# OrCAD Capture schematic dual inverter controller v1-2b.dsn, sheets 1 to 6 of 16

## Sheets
1 Resolver B: size B; rev: V1.2B; company: Wolfspeed; note: 535 W Research Center Blvd.; note: Fayetteville, AR, 72701
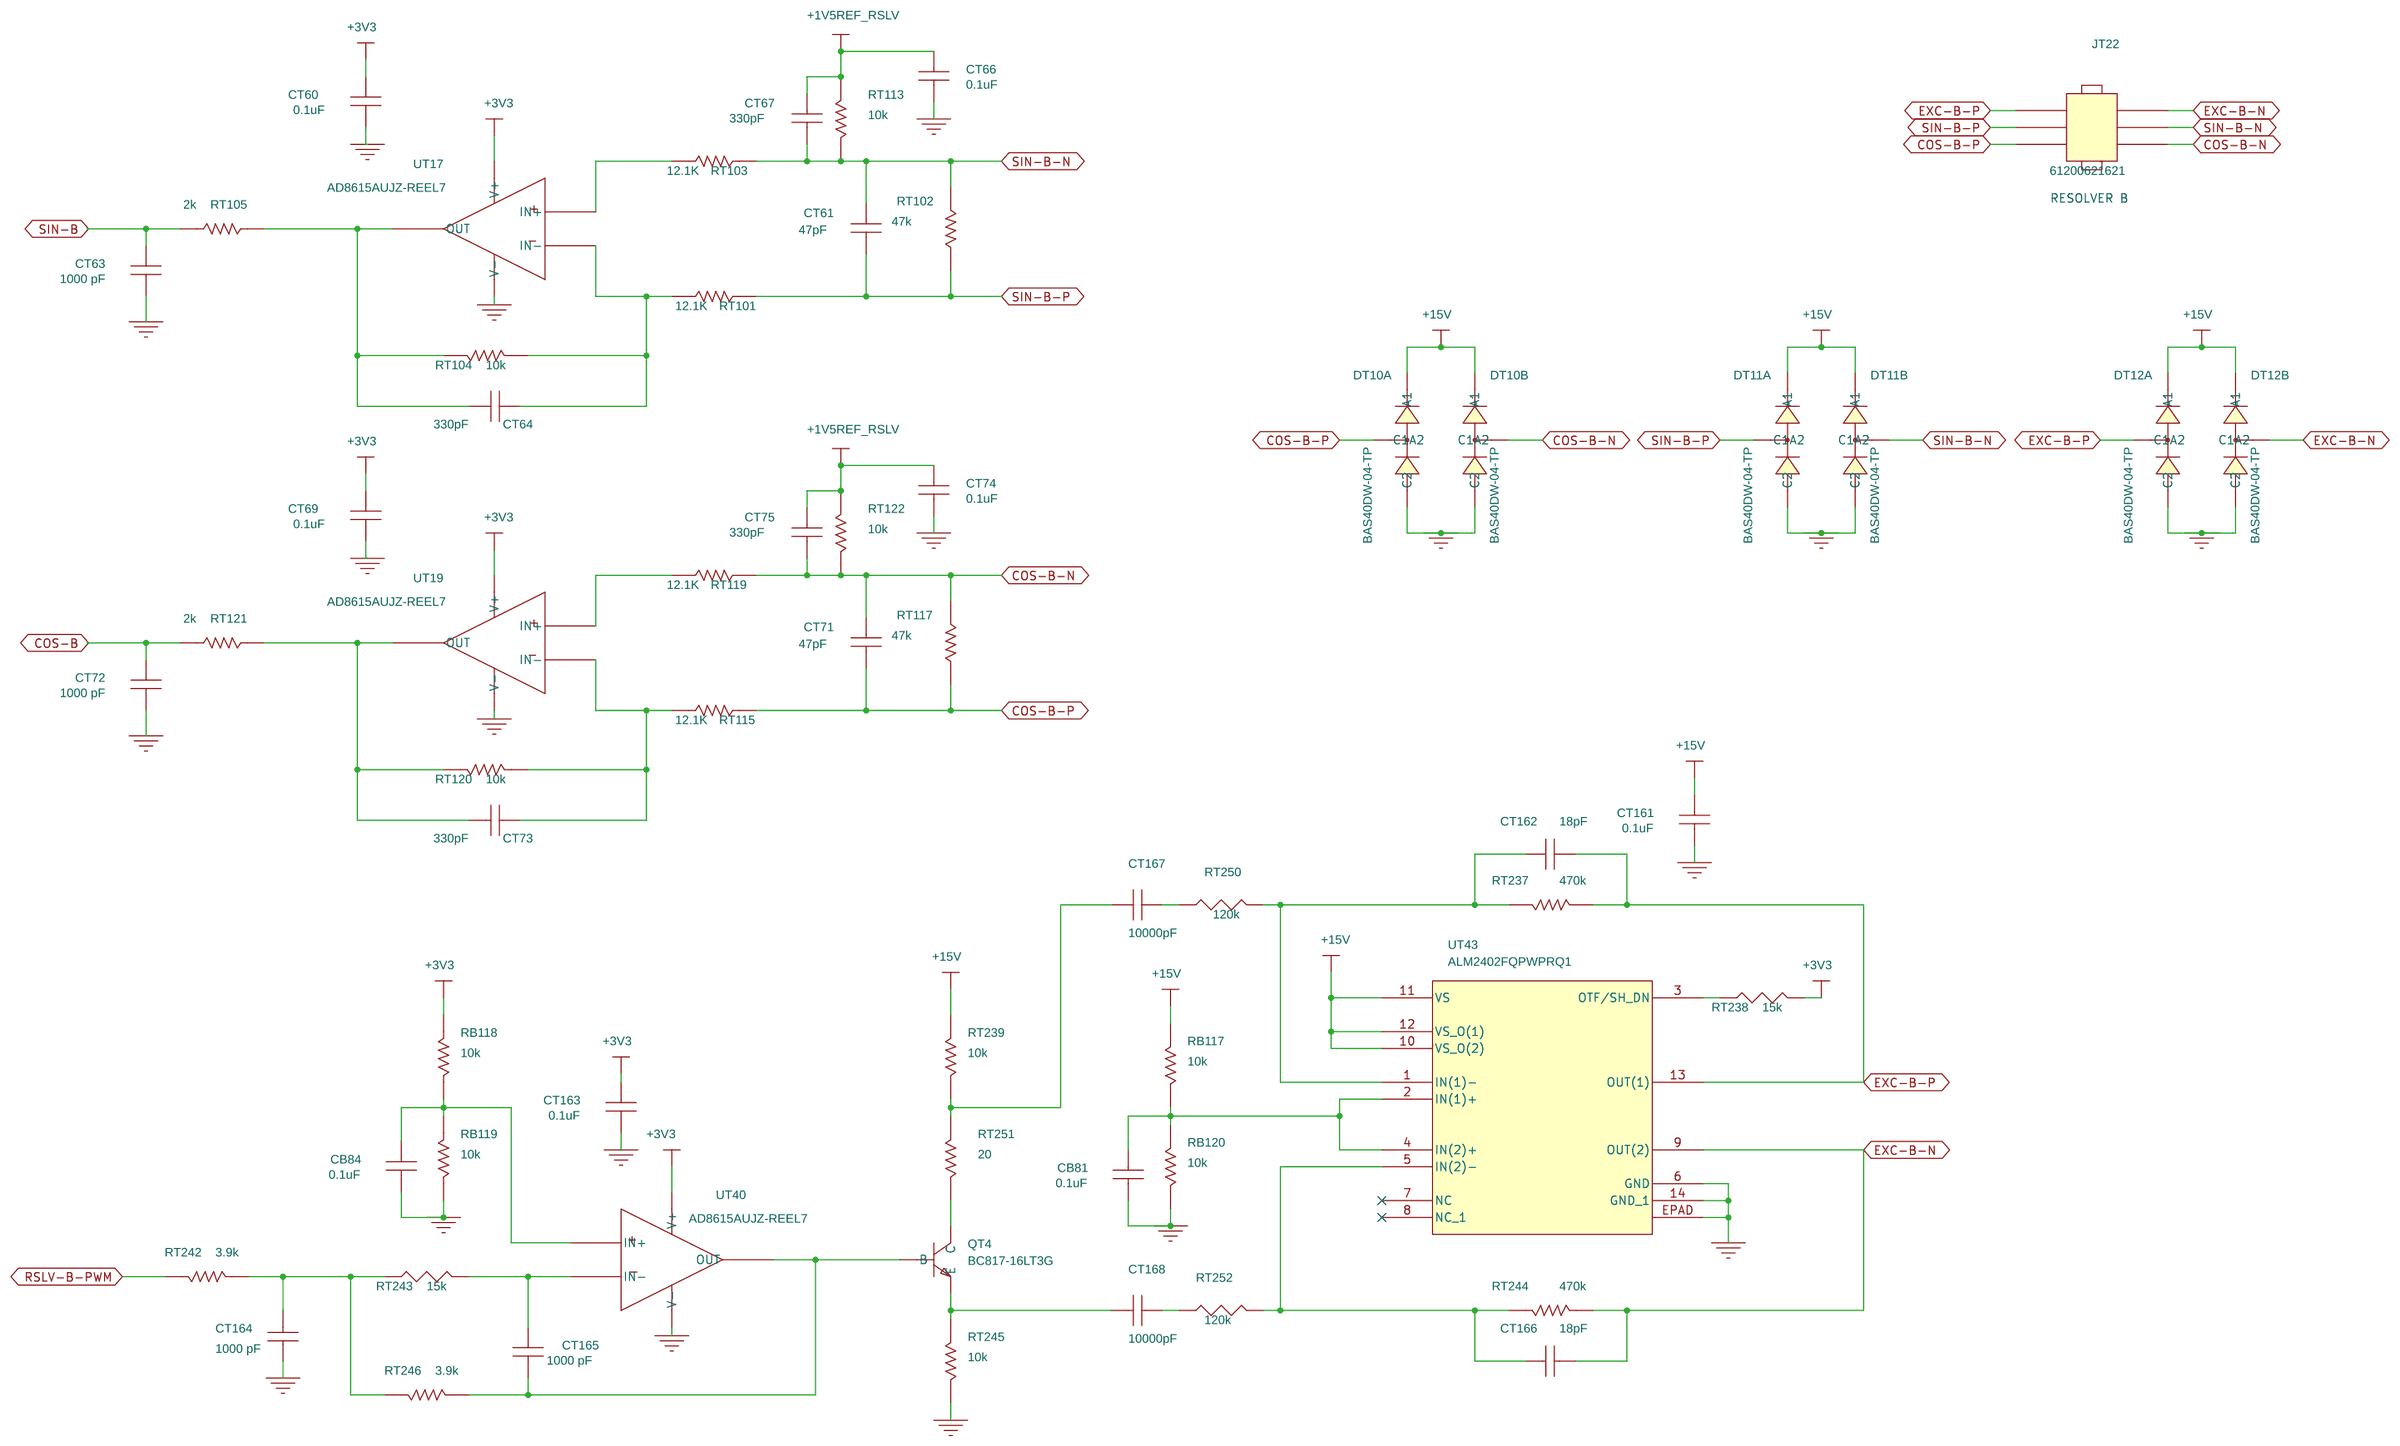
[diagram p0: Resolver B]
2 Resolver A: size B
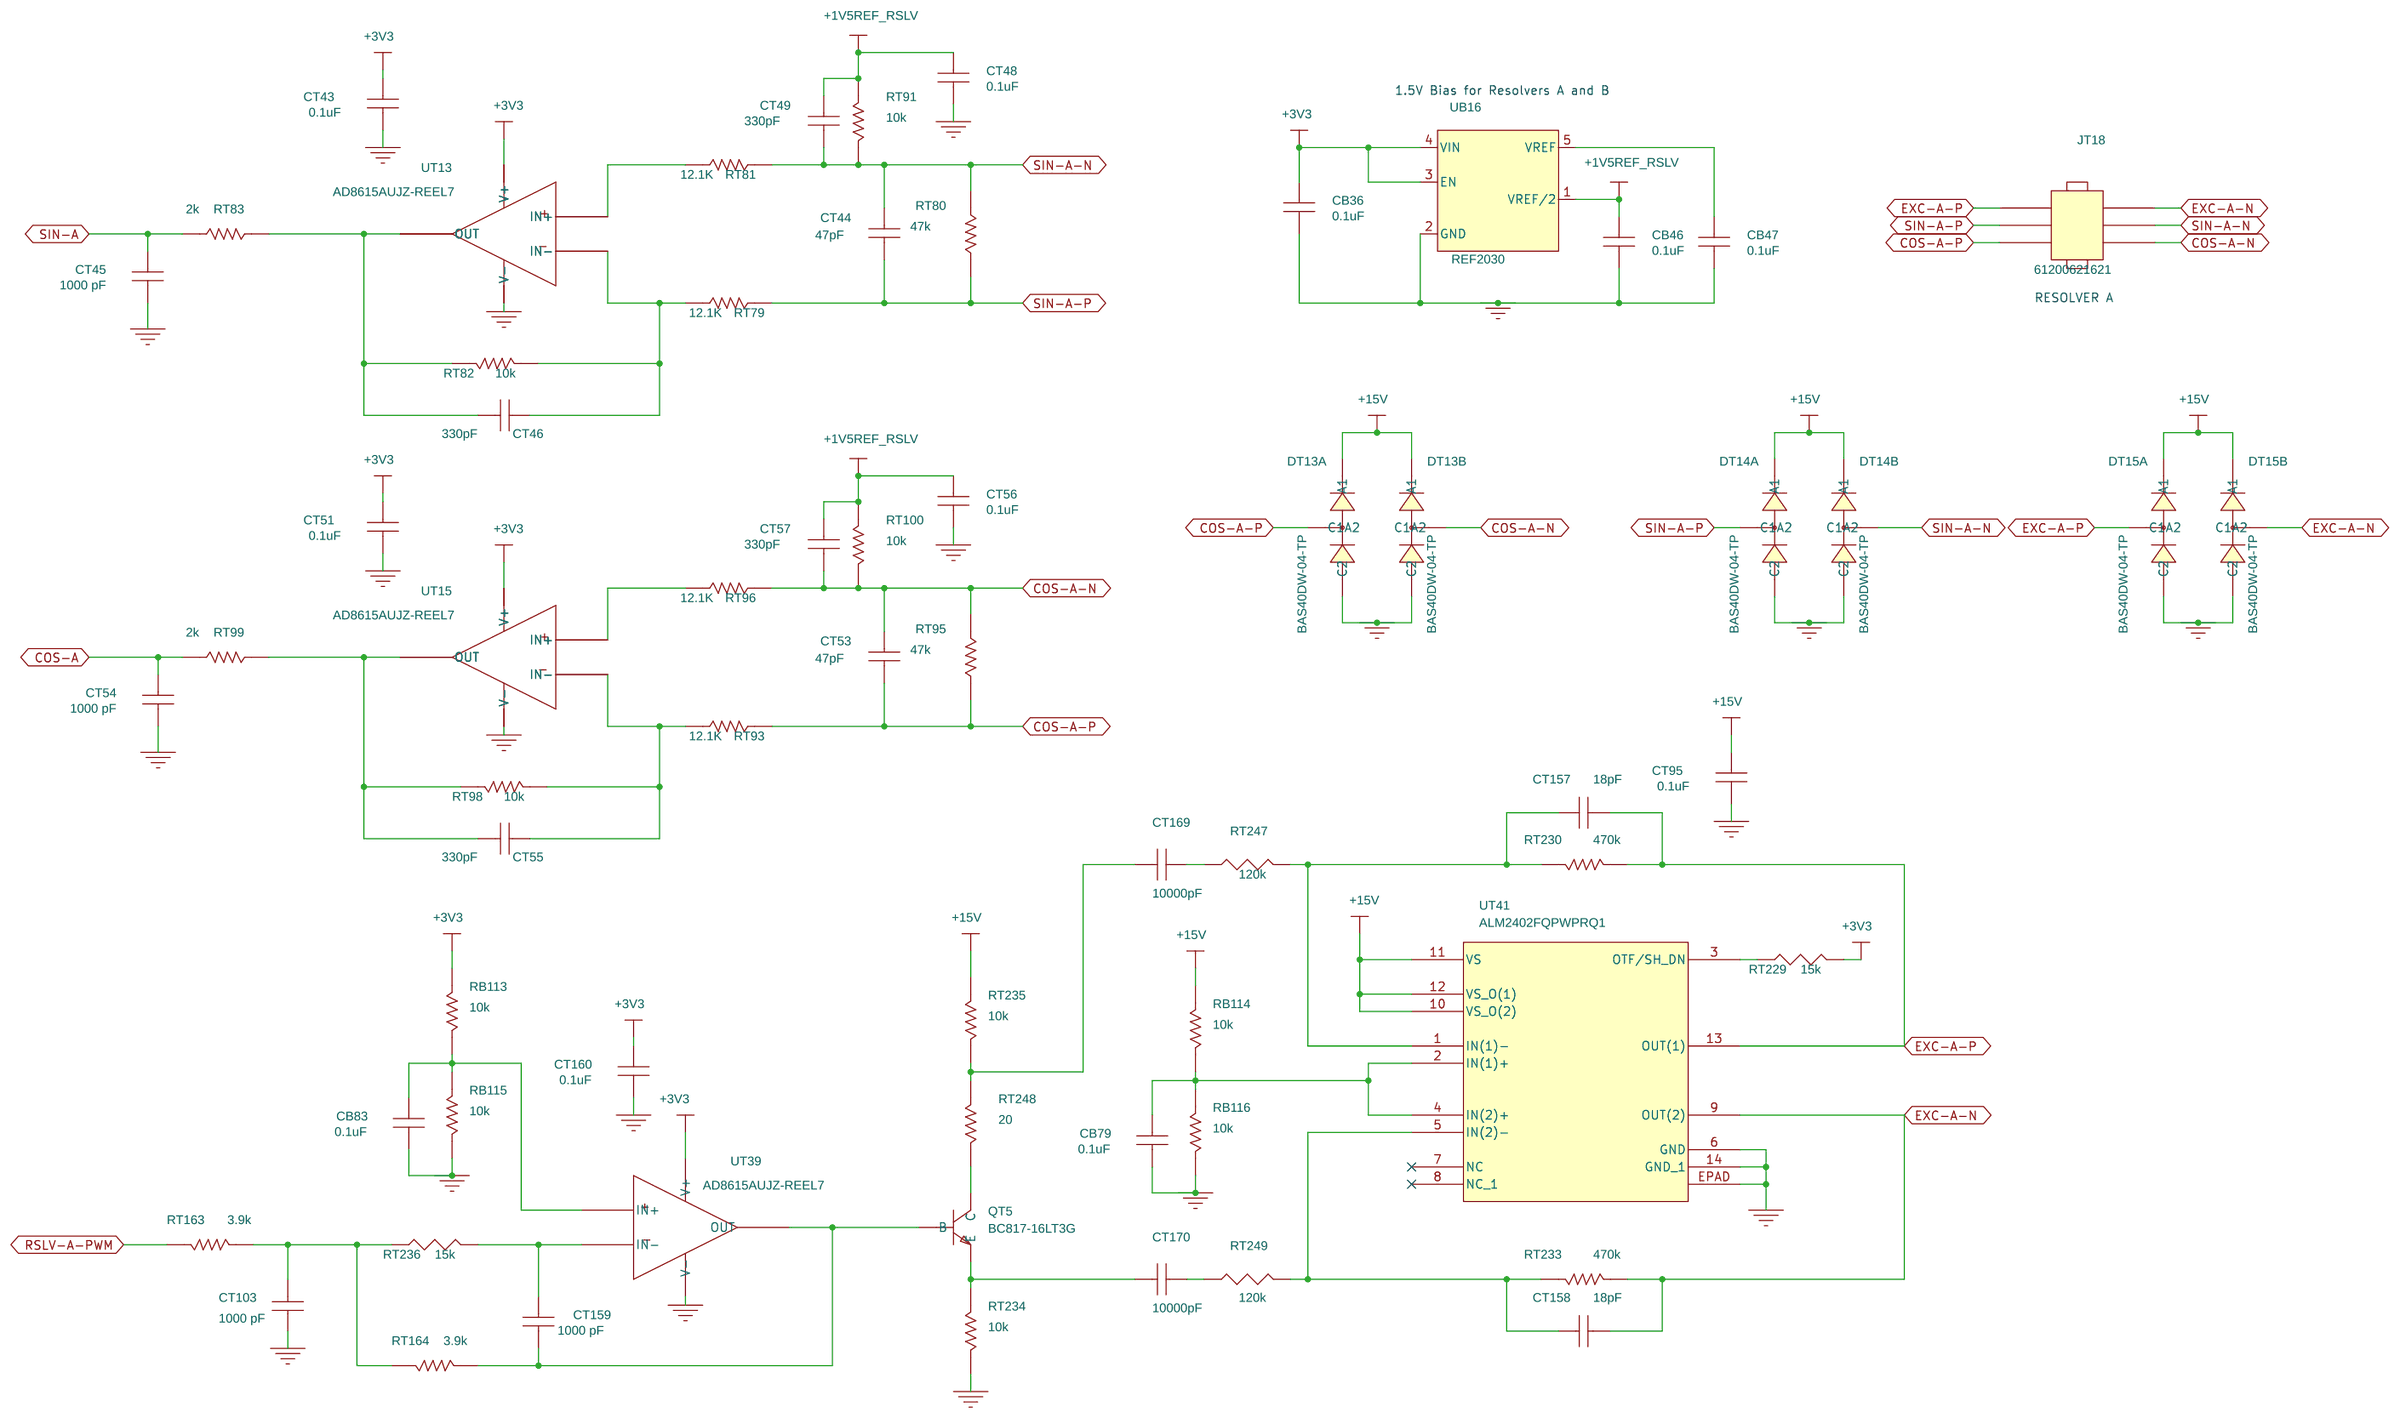
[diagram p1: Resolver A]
3 Test Points: size B; title: Controller
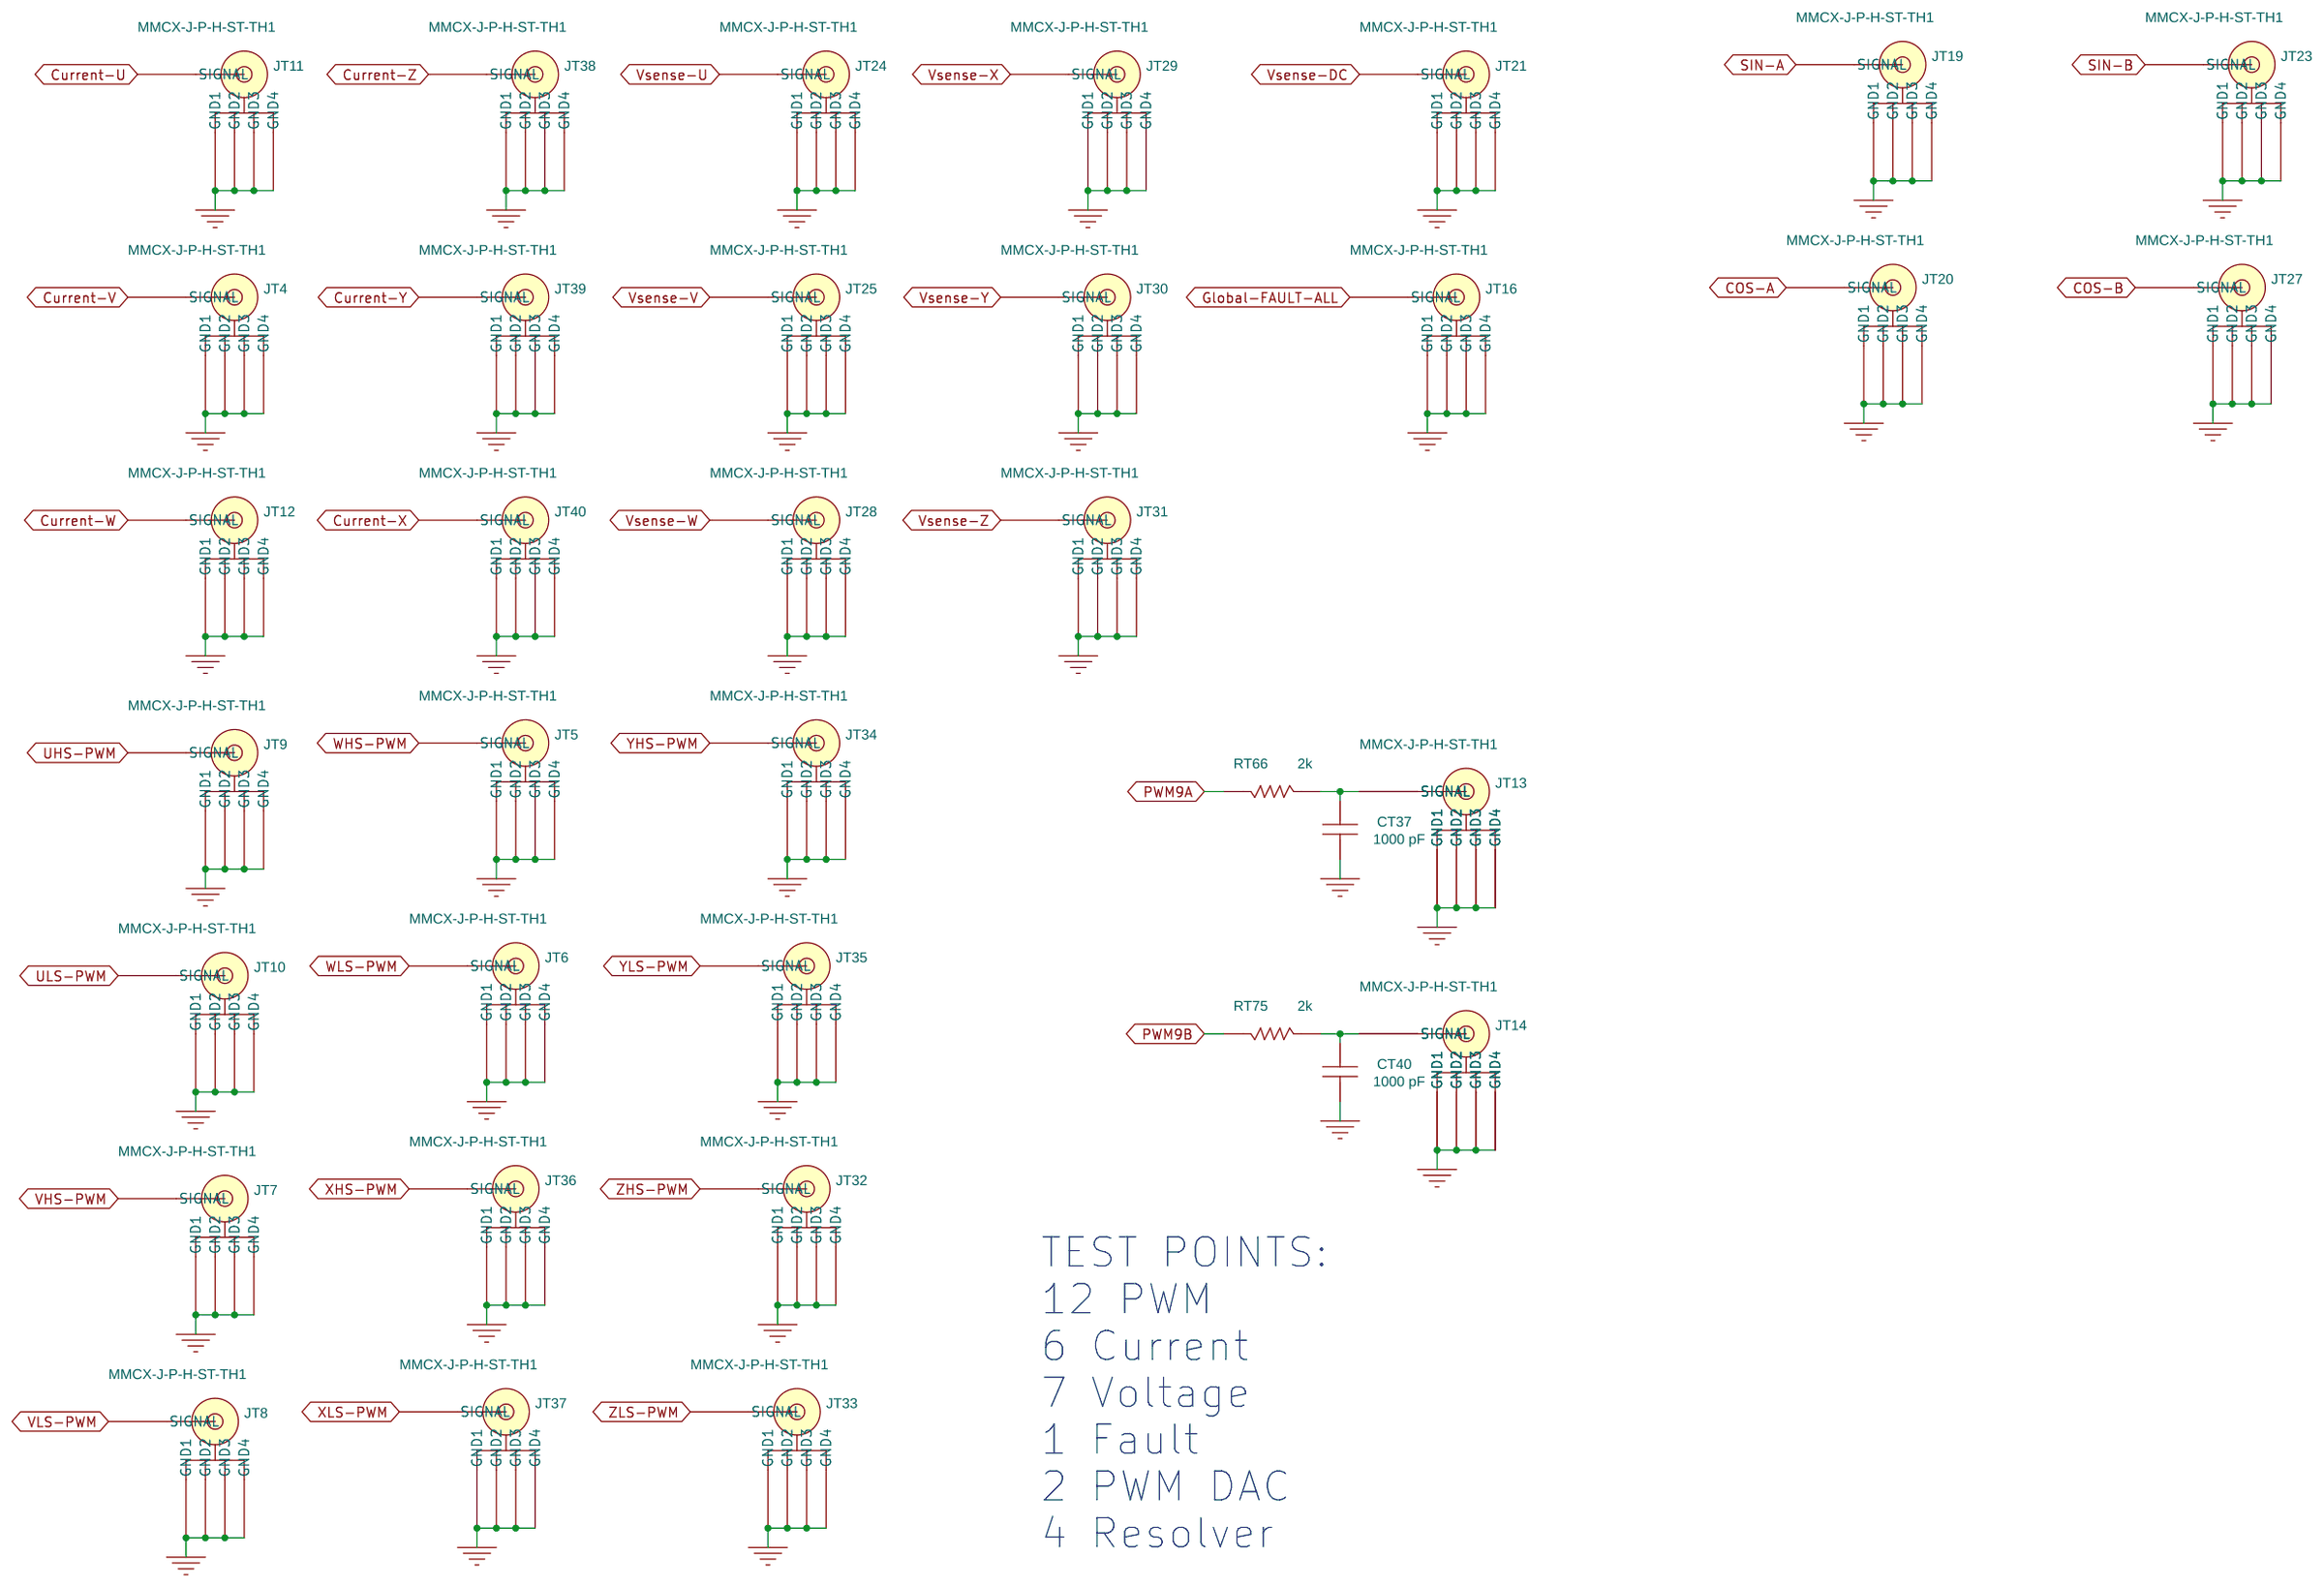
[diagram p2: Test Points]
4 CAN: size A; title: Controller
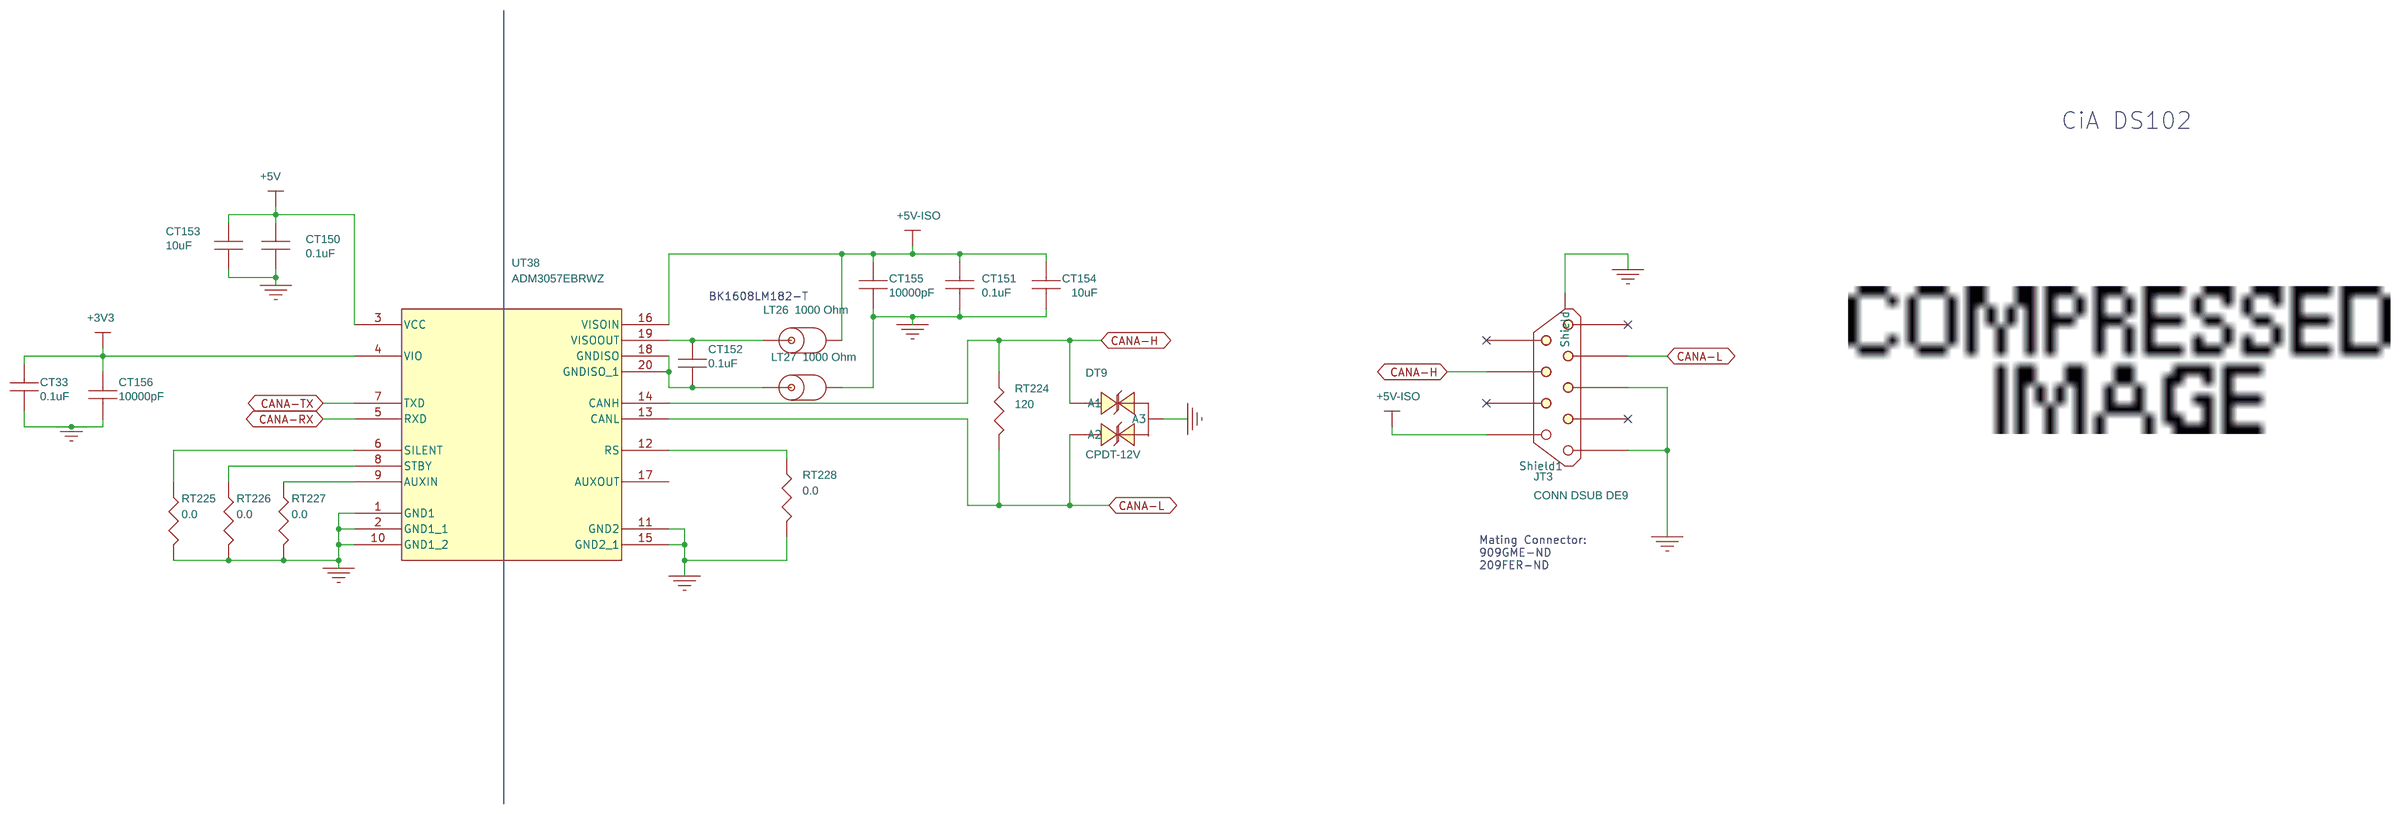
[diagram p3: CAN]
5 ControlCard: size A; title: Controller
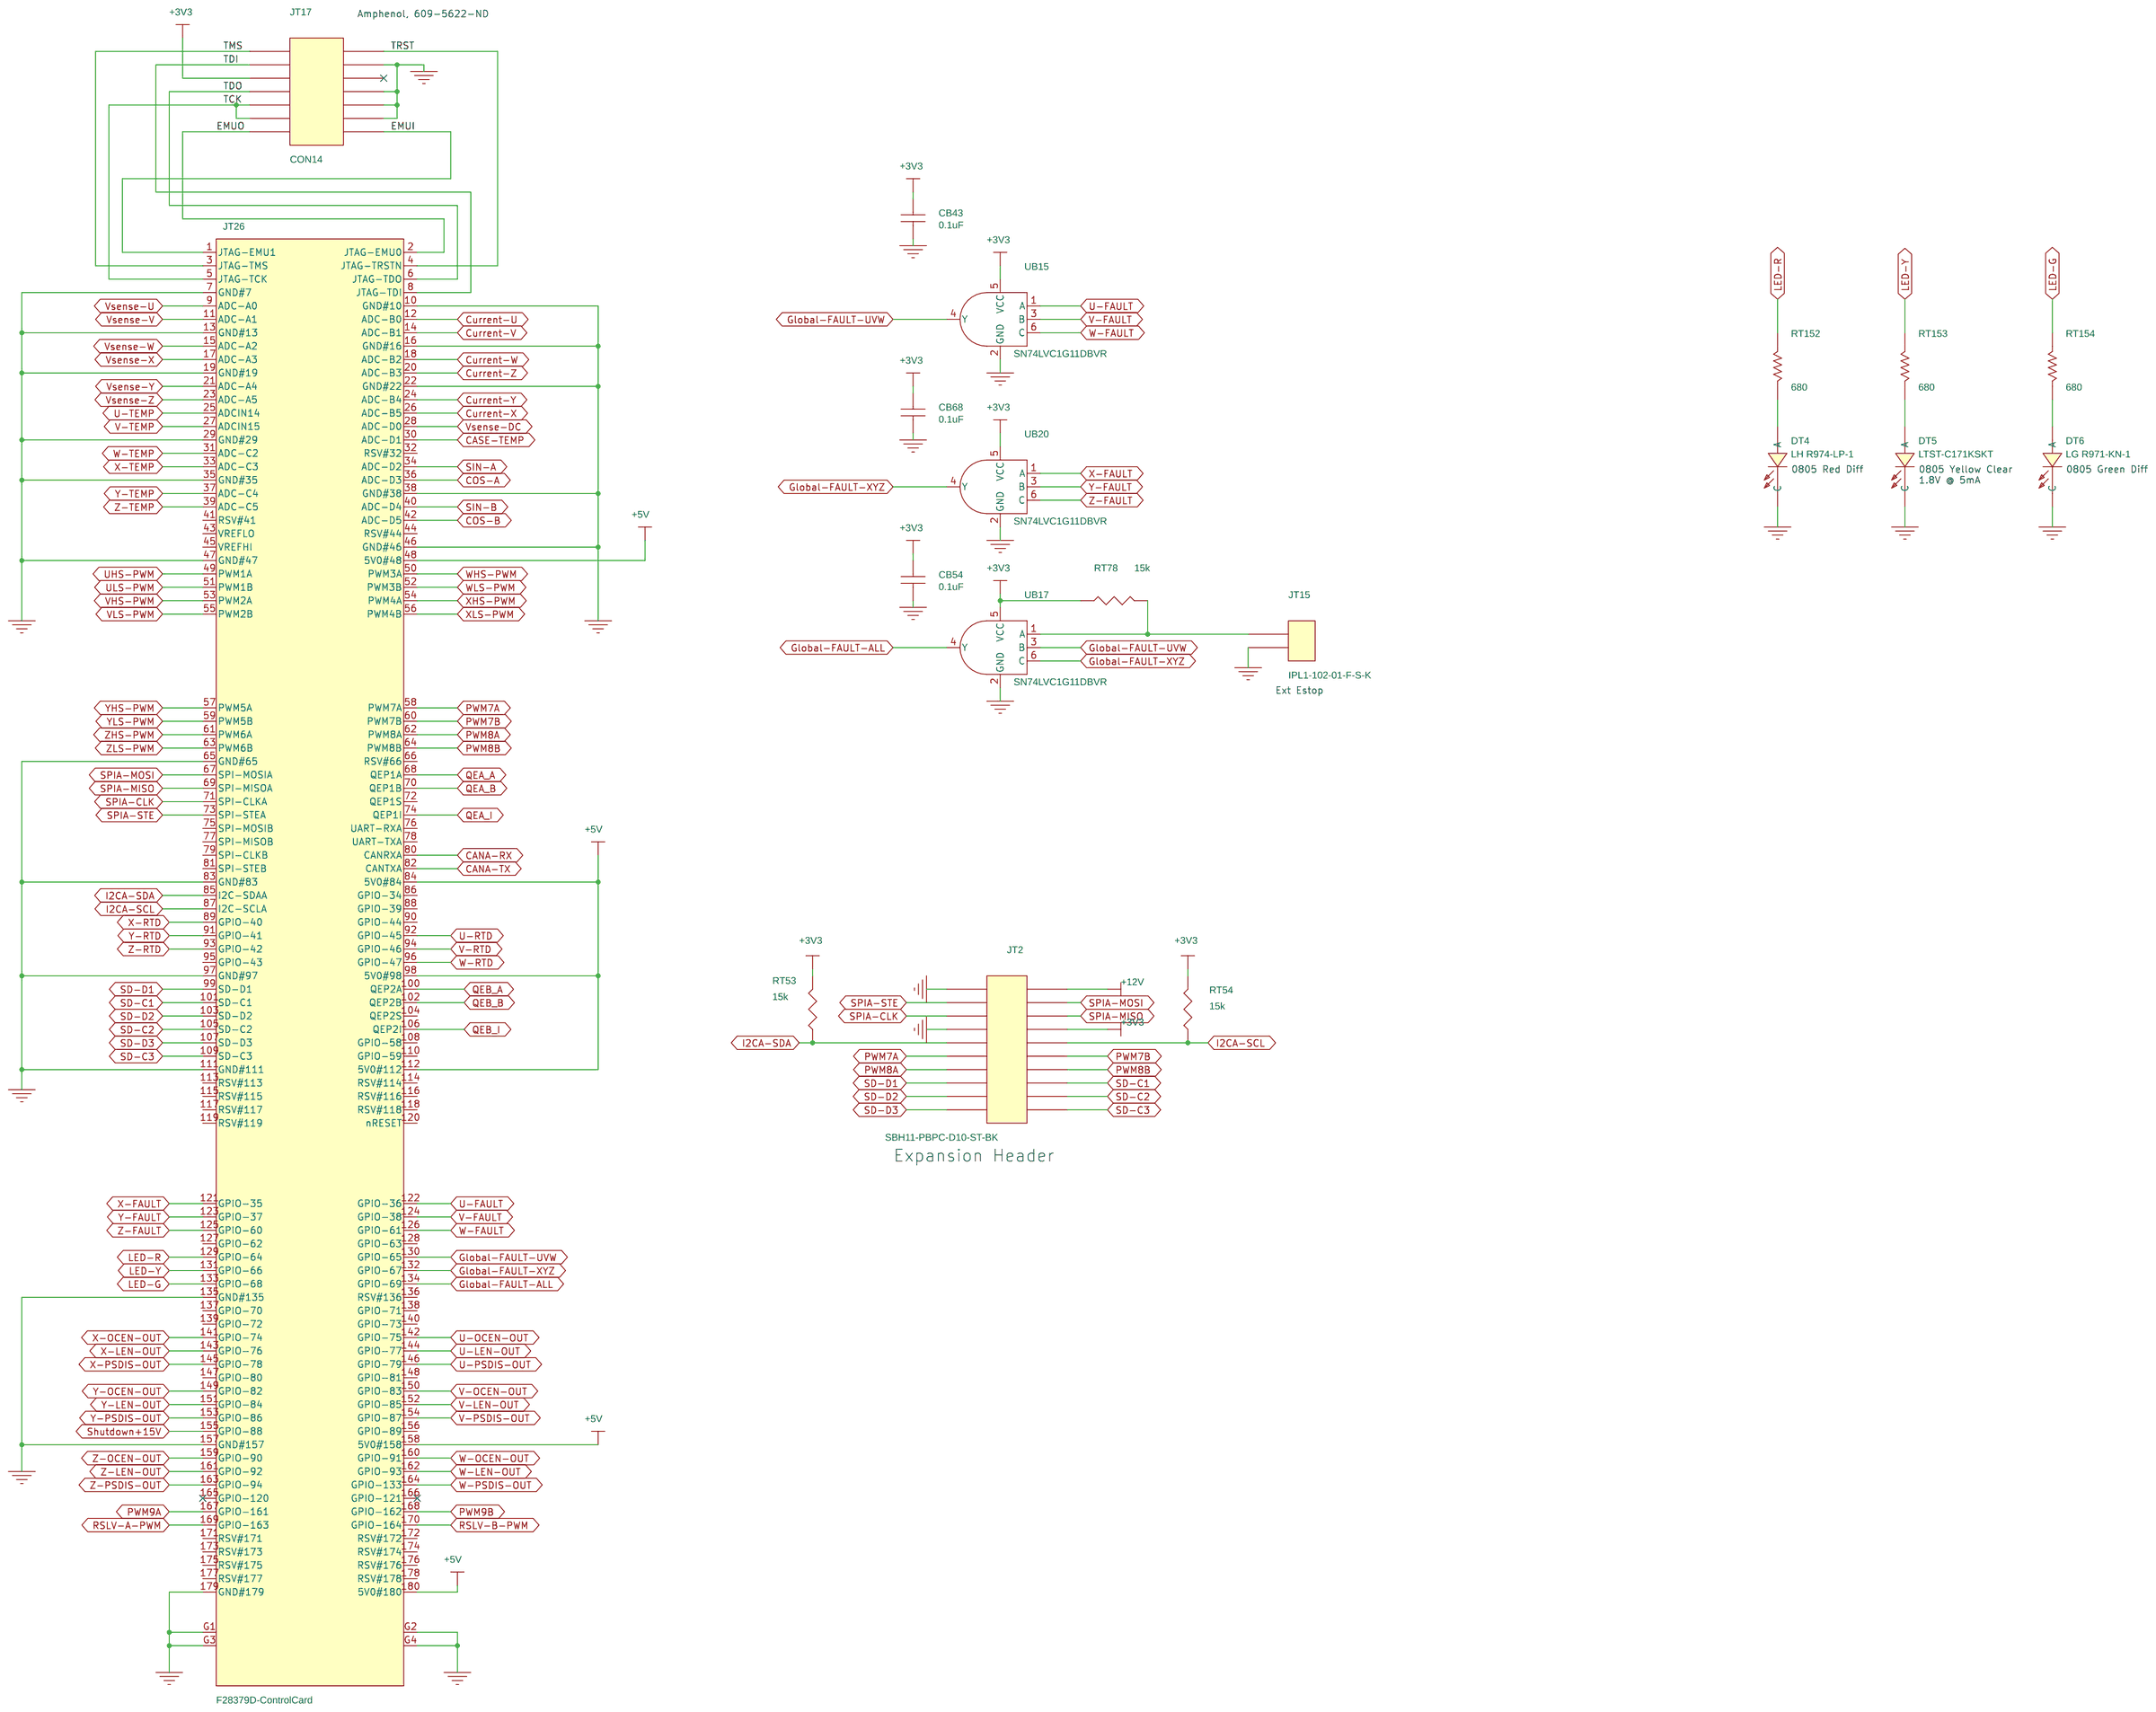
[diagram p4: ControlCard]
6 Current Sensor UVW: size B; title: Controller
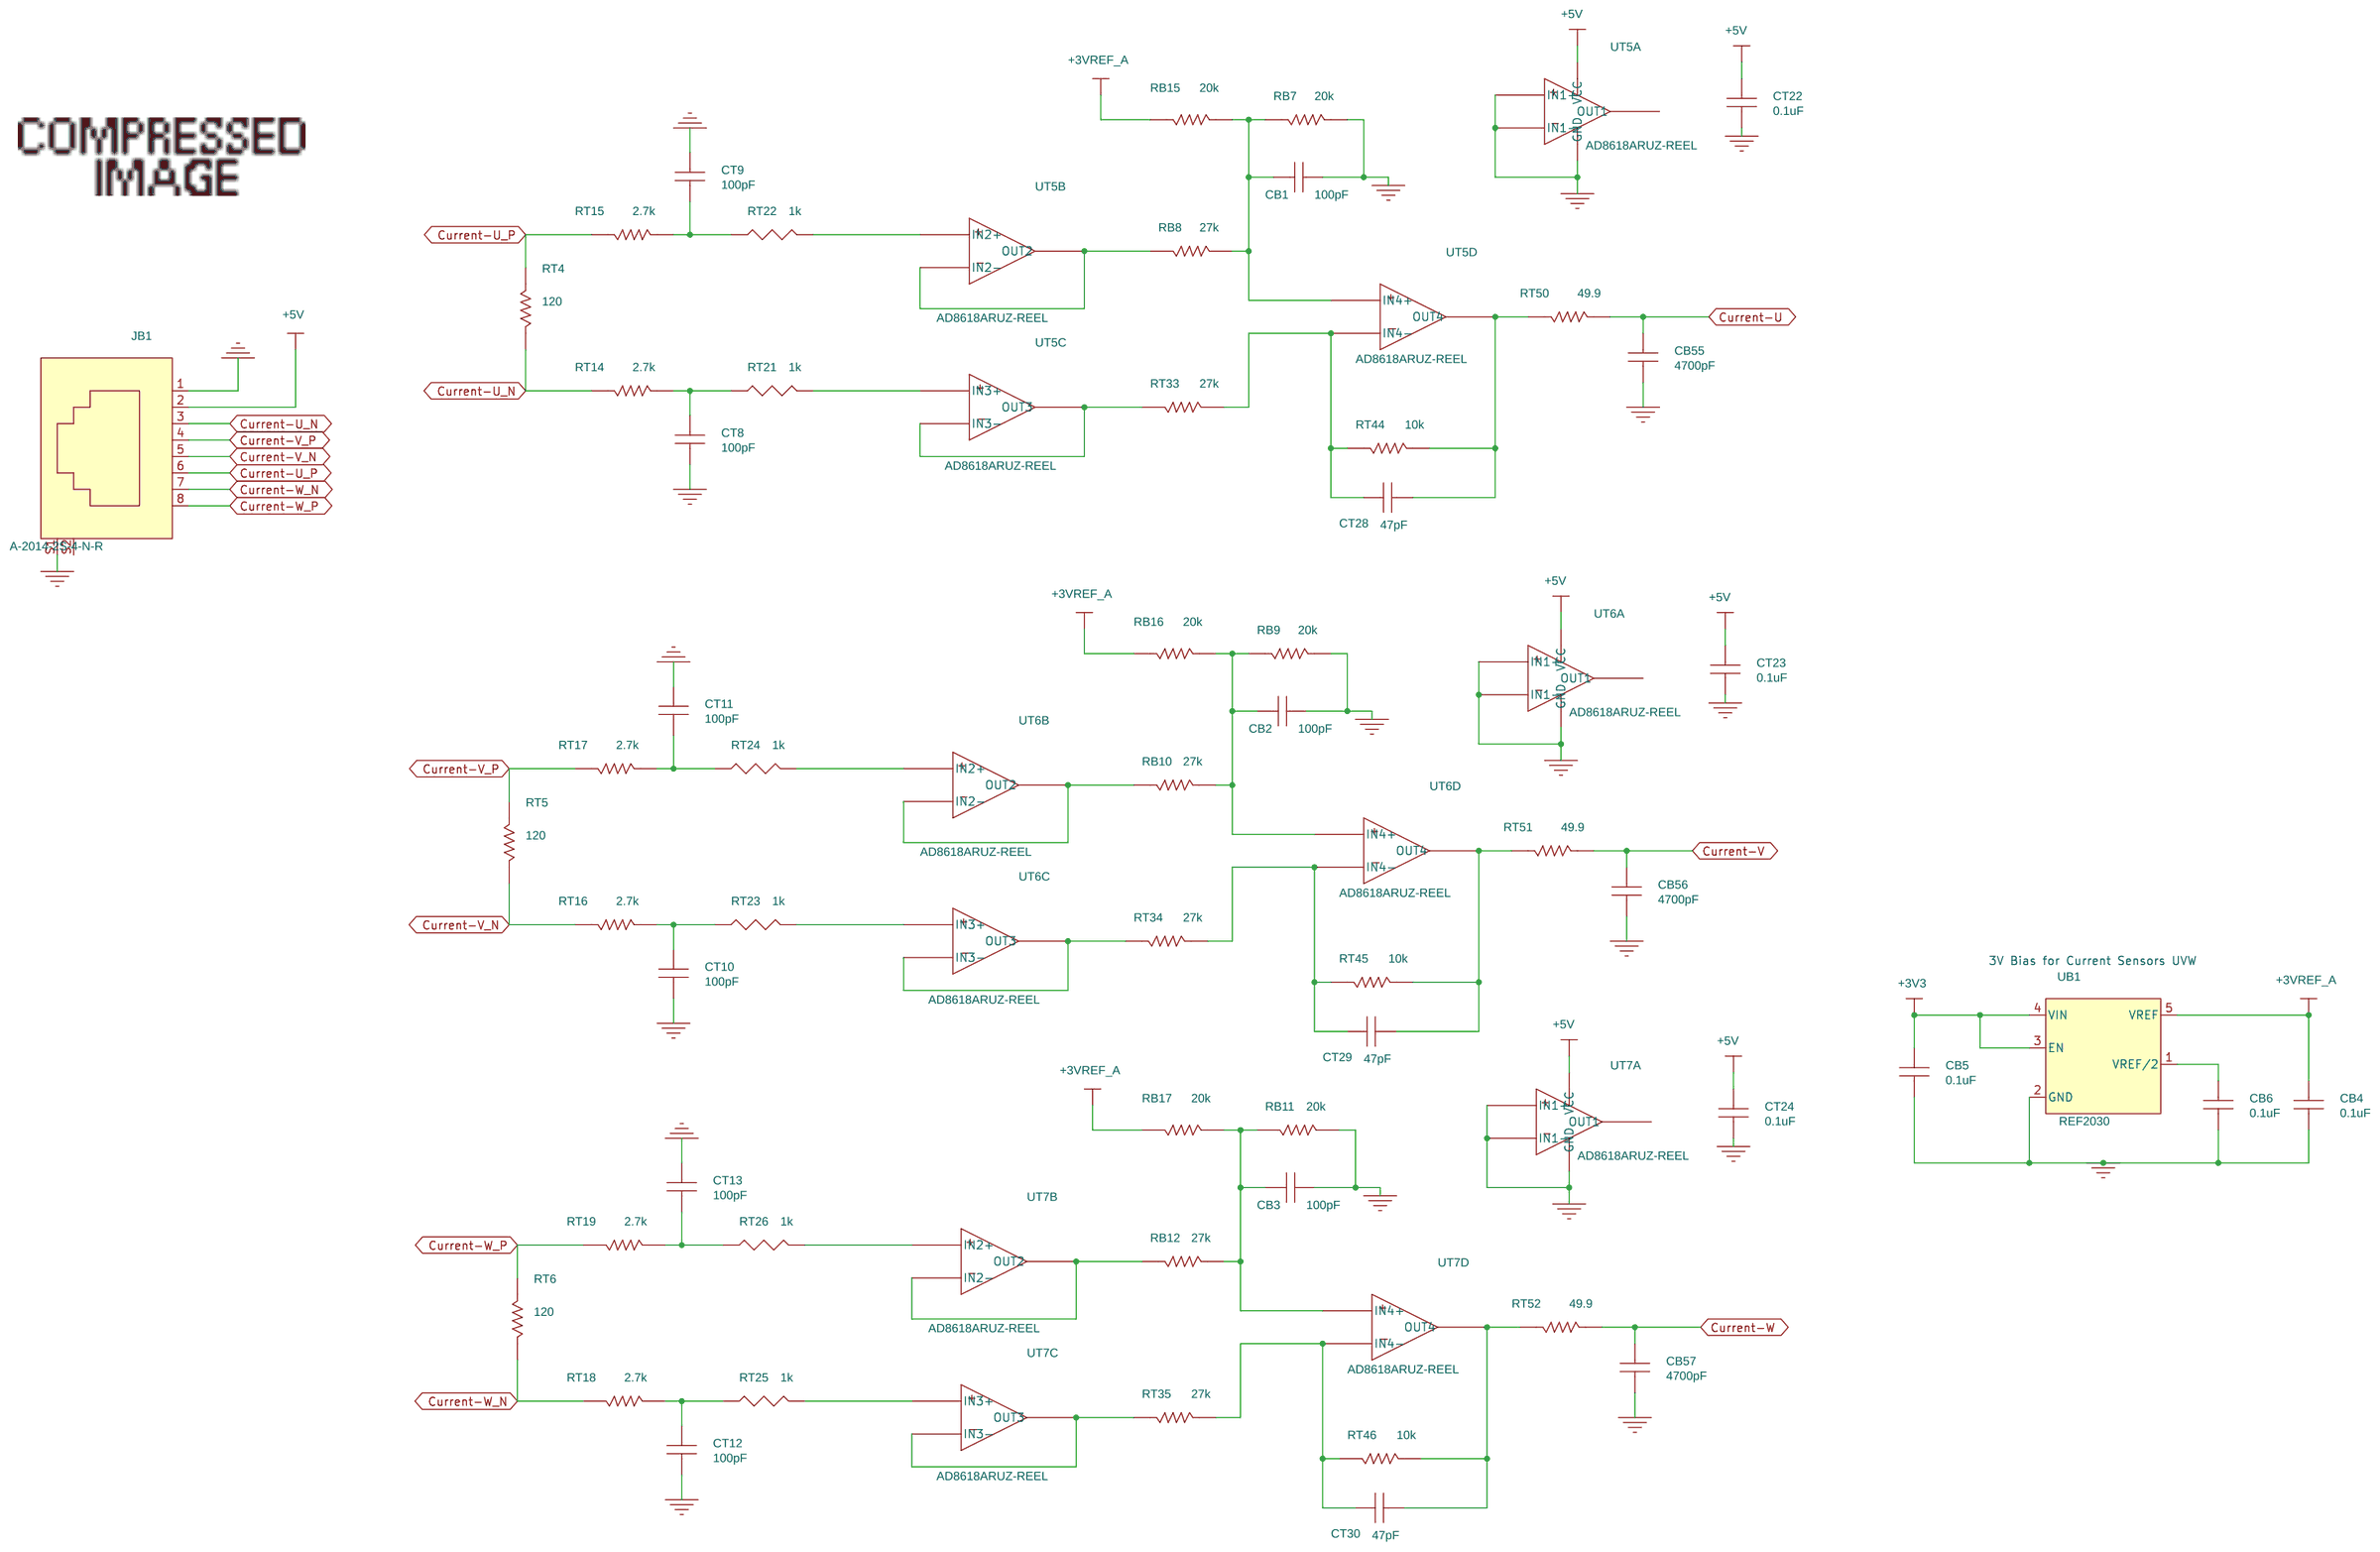
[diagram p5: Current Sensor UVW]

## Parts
sheet CAN
CT33  0.1uF  [CAPC1608X87N]
CT150  0.1uF  [CAPC1608X87N]
CT151  0.1uF  [CAPC1608X87N]
CT152  0.1uF  [CAPC1608X87N]
CT153  10uF  [CAPC2012X135N]
CT154  10uF  [CAPC2012X135N]
CT155  10000pF  [CAPC1608X90N]
CT156  10000pF  [CAPC1608X90N]
DT9  CPDT-12V  [SOT-23-3-D]
JT3  CONN DSUB DE9  [CONN_DE9_M_VERT]
LT26  1000 Ohm  [INDC1608X95N]
LT27  1000 Ohm  [INDC1608X95N]
RT224  120  [RESC1608X55N]
RT225  0.0  [RESC1608X65N]
RT226  0.0  [RESC1608X65N]
RT227  0.0  [RESC1608X65N]
RT228  0.0  [RESC1608X65N]
UT38  ADM3057EBRWZ  [RW-20_ADI]
sheet ControlCard
CB43  0.1uF  [CAPC1608X87N]
CB54  0.1uF  [CAPC1608X87N]
CB68  0.1uF  [CAPC1608X87N]
DT4  LH R974-LP-1  [D_0805]
DT5  LTST-C171KSKT  [D_0805]
DT6  LG R971-KN-1  [D_0805]
JT2  SBH11-PBPC-D10-ST-BK  [CON_2x10_shrouded]
JT15  IPL1-102-01-F-S-K  [CON_1x2_100mil_TH]
JT17  CON14  [JTAG]
JT26  F28379D-ControlCard  [F28379D_ControlCard_corrected]
RT53  15k  [RESC1608X55N]
RT54  15k  [RESC1608X55N]
RT78  15k  [RESC1608X55N]
RT152  680  [RESC1608X55N]
RT153  680  [RESC1608X55N]
RT154  680  [RESC1608X55N]
UB15  SN74LVC1G11DBVR  [SOT_23_6]
UB17  SN74LVC1G11DBVR  [SOT_23_6]
UB20  SN74LVC1G11DBVR  [SOT_23_6]
sheet Current Sensor UVW
CB1  100pF  [CAPC1608X90N]
CB2  100pF  [CAPC1608X90N]
CB3  100pF  [CAPC1608X90N]
CB4  0.1uF  [CAPC1608X87N]
CB5  0.1uF  [CAPC1608X87N]
CB6  0.1uF  [CAPC1608X87N]
CB55  4700pF  [c_0603]
CB56  4700pF  [c_0603]
CB57  4700pF  [c_0603]
CT8  100pF  [CAPC1608X90N]
CT9  100pF  [CAPC1608X90N]
CT10  100pF  [CAPC1608X90N]
CT11  100pF  [CAPC1608X90N]
CT12  100pF  [CAPC1608X90N]
CT13  100pF  [CAPC1608X90N]
CT22  0.1uF  [CAPC1608X87N]
CT23  0.1uF  [CAPC1608X87N]
CT24  0.1uF  [CAPC1608X87N]
CT28  47pF  [CAPC1608X87N]
CT29  47pF  [CAPC1608X87N]
CT30  47pF  [CAPC1608X87N]
JB1  A-2014-2S-4-N-R  [RJ45_VERT_SHIELD_CON]
RB7  20k  [RESC1608X55N]
RB8  27k  [RESC1608X55N]
RB9  20k  [RESC1608X55N]
RB10  27k  [RESC1608X55N]
RB11  20k  [RESC1608X55N]
RB12  27k  [RESC1608X55N]
RB15  20k  [RESC1608X55N]
RB16  20k  [RESC1608X55N]
RB17  20k  [RESC1608X55N]
RT4  120  [RESC1608X55N]
RT5  120  [RESC1608X55N]
RT6  120  [RESC1608X55N]
RT14  2.7k  [RESC1608X55N]
RT15  2.7k  [RESC1608X55N]
RT16  2.7k  [RESC1608X55N]
RT17  2.7k  [RESC1608X55N]
RT18  2.7k  [RESC1608X55N]
RT19  2.7k  [RESC1608X55N]
RT21  1k  [RESC1608X55N]
RT22  1k  [RESC1608X55N]
RT23  1k  [RESC1608X55N]
RT24  1k  [RESC1608X55N]
RT25  1k  [RESC1608X55N]
RT26  1k  [RESC1608X55N]
RT33  27k  [RESC1608X55N]
RT34  27k  [RESC1608X55N]
RT35  27k  [RESC1608X55N]
RT44  10k  [RESC1608X55N]
RT45  10k  [RESC1608X55N]
RT46  10k  [RESC1608X55N]
RT50  49.9  [RESC1608X55N]
RT51  49.9  [RESC1608X55N]
RT52  49.9  [RESC1608X55N]
UB1  REF2030  [SOT23-5_0_95X2_70P_H1_45]
UT5  AD8618ARUZ-REEL  [TSSOP-14]  (sections A,B,C,D)
UT6  AD8618ARUZ-REEL  [TSSOP-14]  (sections A,B,C,D)
UT7  AD8618ARUZ-REEL  [TSSOP-14]  (sections A,B,C,D)
sheet Resolver A
CB36  0.1uF  [CAPC1608X87N]
CB46  0.1uF  [CAPC1608X87N]
CB47  0.1uF  [CAPC1608X87N]
CB79  0.1uF  [CAPC1608X87N]
CB83  0.1uF  [CAPC1608X87N]
CT43  0.1uF  [CAPC1608X87N]
CT44  47pF  [CAPC1608X87N]
CT45  1000 pF  [CAPC1608X90N]
CT46  330pF  [CAPC1608X87N]
CT48  0.1uF  [CAPC1608X87N]
CT49  330pF  [CAPC1608X87N]
CT51  0.1uF  [CAPC1608X87N]
CT53  47pF  [CAPC1608X87N]
CT54  1000 pF  [CAPC1608X90N]
CT55  330pF  [CAPC1608X87N]
CT56  0.1uF  [CAPC1608X87N]
CT57  330pF  [CAPC1608X87N]
CT95  0.1uF  [CAPC1608X87N]
CT103  1000 pF  [CAPC1608X87N]
CT157  18pF  [CAPC1608X90N]
CT158  18pF  [CAPC1608X90N]
CT159  1000 pF  [CAPC1608X90N]
CT160  0.1uF  [CAPC1608X87N]
CT169  10000pF  [CAPC1608X90N]
CT170  10000pF  [CAPC1608X90N]
DT13  BAS40DW-04-TP  [SOT363_NEX]  (sections A,B)
DT14  BAS40DW-04-TP  [SOT363_NEX]  (sections A,B)
DT15  BAS40DW-04-TP  [SOT363_NEX]  (sections A,B)
JT18  61200621621  [A26815-ND]
QT5  BC817-16LT3G  [SOT_23_3]
RB113  10k  [RESC1608X55N]
RB114  10k  [RESC1608X55N]
RB115  10k  [RESC1608X55N]
RB116  10k  [RESC1608X55N]
RT79  12.1K  [RESC1608X55N]
RT80  47k  [RESC1608X55N]
RT81  12.1K  [RESC1608X55N]
RT82  10k  [RESC1608X55N]
RT83  2k  [RESC1608X55N]
RT91  10k  [RESC1608X55N]
RT93  12.1K  [RESC1608X55N]
RT95  47k  [RESC1608X55N]
RT96  12.1K  [RESC1608X55N]
RT98  10k  [RESC1608X55N]
RT99  2k  [RESC1608X55N]
RT100  10k  [RESC1608X55N]
RT163  3.9k  [RESC1608X55N]
RT164  3.9k  [RESC1608X55N]
RT229  15k  [RESC1608X55N]
RT230  470k  [RESC1608X55N]
RT233  470k  [RESC1608X55N]
RT234  10k  [RESC1608X55N]
RT235  10k  [RESC1608X55N]
RT236  15k  [RESC1608X55N]
RT247  120k  [RESC1608X55N]
RT248  20  [RESC1608X55N]
RT249  120k  [RESC1608X55N]
UB16  REF2030  [SOT23-5_0_95X2_70P_H1_45]
UT13  AD8615AUJZ-REEL7  [sot23-5_0_95x2_70p_h1_22]
UT15  AD8615AUJZ-REEL7  [sot23-5_0_95x2_70p_h1_22]
UT39  AD8615AUJZ-REEL7  [sot23-5_0_95x2_70p_h1_22]
UT41  ALM2402FQPWPRQ1  [HTSSOP14_5X4P4_TEX]
sheet Resolver B
CB81  0.1uF  [CAPC1608X87N]
CB84  0.1uF  [CAPC1608X87N]
CT60  0.1uF  [CAPC1608X87N]
CT61  47pF  [CAPC1608X87N]
CT63  1000 pF  [CAPC1608X90N]
CT64  330pF  [CAPC1608X87N]
CT66  0.1uF  [CAPC1608X87N]
CT67  330pF  [CAPC1608X87N]
CT69  0.1uF  [CAPC1608X87N]
CT71  47pF  [CAPC1608X87N]
CT72  1000 pF  [CAPC1608X90N]
CT73  330pF  [CAPC1608X87N]
CT74  0.1uF  [CAPC1608X87N]
CT75  330pF  [CAPC1608X87N]
CT161  0.1uF  [CAPC1608X87N]
CT162  18pF  [CAPC1608X90N]
CT163  0.1uF  [CAPC1608X87N]
CT164  1000 pF  [CAPC1608X87N]
CT165  1000 pF  [CAPC1608X90N]
CT166  18pF  [CAPC1608X90N]
CT167  10000pF  [CAPC1608X90N]
CT168  10000pF  [CAPC1608X90N]
DT10  BAS40DW-04-TP  [SOT363_NEX]  (sections A,B)
DT11  BAS40DW-04-TP  [SOT363_NEX]  (sections A,B)
DT12  BAS40DW-04-TP  [SOT363_NEX]  (sections A,B)
JT22  61200621621  [A26815-ND]
QT4  BC817-16LT3G  [SOT_23_3]
RB117  10k  [RESC1608X55N]
RB118  10k  [RESC1608X55N]
RB119  10k  [RESC1608X55N]
RB120  10k  [RESC1608X55N]
RT101  12.1K  [RESC1608X55N]
RT102  47k  [RESC1608X55N]
RT103  12.1K  [RESC1608X55N]
RT104  10k  [RESC1608X55N]
RT105  2k  [RESC1608X55N]
RT113  10k  [RESC1608X55N]
RT115  12.1K  [RESC1608X55N]
RT117  47k  [RESC1608X55N]
RT119  12.1K  [RESC1608X55N]
RT120  10k  [RESC1608X55N]
RT121  2k  [RESC1608X55N]
RT122  10k  [RESC1608X55N]
RT237  470k  [RESC1608X55N]
RT238  15k  [RESC1608X55N]
RT239  10k  [RESC1608X55N]
RT242  3.9k  [RESC1608X55N]
RT243  15k  [RESC1608X55N]
RT244  470k  [RESC1608X55N]
RT245  10k  [RESC1608X55N]
RT246  3.9k  [RESC1608X55N]
RT250  120k  [RESC1608X55N]
RT251  20  [RESC1608X55N]
RT252  120k  [RESC1608X55N]
UT17  AD8615AUJZ-REEL7  [sot23-5_0_95x2_70p_h1_22]
UT19  AD8615AUJZ-REEL7  [sot23-5_0_95x2_70p_h1_22]
UT40  AD8615AUJZ-REEL7  [sot23-5_0_95x2_70p_h1_22]
UT43  ALM2402FQPWPRQ1  [HTSSOP14_5X4P4_TEX]
sheet Test Points
CT37  1000 pF  [CAPC1608X90N]
CT40  1000 pF  [CAPC1608X90N]
JT4  MMCX-J-P-H-ST-TH1  [MMCX_PLUG_TH]
JT5  MMCX-J-P-H-ST-TH1  [MMCX_PLUG_TH]
JT6  MMCX-J-P-H-ST-TH1  [MMCX_PLUG_TH]
JT7  MMCX-J-P-H-ST-TH1  [MMCX_PLUG_TH]
JT8  MMCX-J-P-H-ST-TH1  [MMCX_PLUG_TH]
JT9  MMCX-J-P-H-ST-TH1  [MMCX_PLUG_TH]
JT10  MMCX-J-P-H-ST-TH1  [MMCX_PLUG_TH]
JT11  MMCX-J-P-H-ST-TH1  [MMCX_PLUG_TH]
JT12  MMCX-J-P-H-ST-TH1  [MMCX_PLUG_TH]
JT13  MMCX-J-P-H-ST-TH1  [MMCX_PLUG_TH]
JT14  MMCX-J-P-H-ST-TH1  [MMCX_PLUG_TH]
JT16  MMCX-J-P-H-ST-TH1  [MMCX_PLUG_TH]
JT19  MMCX-J-P-H-ST-TH1  [MMCX_PLUG_TH]
JT20  MMCX-J-P-H-ST-TH1  [MMCX_PLUG_TH]
JT21  MMCX-J-P-H-ST-TH1  [MMCX_PLUG_TH]
JT23  MMCX-J-P-H-ST-TH1  [MMCX_PLUG_TH]
JT24  MMCX-J-P-H-ST-TH1  [MMCX_PLUG_TH]
JT25  MMCX-J-P-H-ST-TH1  [MMCX_PLUG_TH]
JT27  MMCX-J-P-H-ST-TH1  [MMCX_PLUG_TH]
JT28  MMCX-J-P-H-ST-TH1  [MMCX_PLUG_TH]
JT29  MMCX-J-P-H-ST-TH1  [MMCX_PLUG_TH]
JT30  MMCX-J-P-H-ST-TH1  [MMCX_PLUG_TH]
JT31  MMCX-J-P-H-ST-TH1  [MMCX_PLUG_TH]
JT32  MMCX-J-P-H-ST-TH1  [MMCX_PLUG_TH]
JT33  MMCX-J-P-H-ST-TH1  [MMCX_PLUG_TH]
JT34  MMCX-J-P-H-ST-TH1  [MMCX_PLUG_TH]
JT35  MMCX-J-P-H-ST-TH1  [MMCX_PLUG_TH]
JT36  MMCX-J-P-H-ST-TH1  [MMCX_PLUG_TH]
JT37  MMCX-J-P-H-ST-TH1  [MMCX_PLUG_TH]
JT38  MMCX-J-P-H-ST-TH1  [MMCX_PLUG_TH]
JT39  MMCX-J-P-H-ST-TH1  [MMCX_PLUG_TH]
JT40  MMCX-J-P-H-ST-TH1  [MMCX_PLUG_TH]
RT66  2k  [RESC1608X55N]
RT75  2k  [RESC1608X55N]

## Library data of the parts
CB4-CB6 CB36 CB43 CB46 CB47 CB54 CB68 CB79 CB81 CB83 CB84 CT22-CT24 CT33 CT43 CT48 CT51 CT56 CT60 CT66 CT69 CT74 CT95 CT150-CT152 CT160 CT161 CT163 = CAP: CAP CER 0.1UF 25V X7R 0603; CLASS: DISCRETE; Company Part Status: New; Dielectric Type: Capacitors; Manufacturer: Kemet; Manufacturer PN: C0603C104K3RACTU; PART_NUMBER: TMP-847; Package Size: 0603 (1608 Metric); Rated Voltage: 25V; Temperature Coefficient: X7R; Tolerance: 10%
CT153 CT154 = CAP: CAP CER 10UF 25V X7S 0805; CLASS: DISCRETE; Company Part Status: New; Dielectric Type: Capacitors; Manufacturer: Murata Electronics North America; Manufacturer PN: GRM21BC71E106KE11L; PART_NUMBER: TMP-1080; Package Size: 0805 (2012 Metric); Rated Voltage: 25V; Temperature Coefficient: X7S; Tolerance: 10%
CT155 CT156 CT167-CT170 = CAP: CAP CER 10000PF 25V 10% X7R 0603; CLASS: DISCRETE; Company Part Status: New; Dielectric Type: Capacitors; Manufacturer: Samsung Electro-Mechanics America, Inc.; Manufacturer PN: CL10B103KA8NNNC; PART_NUMBER: TMP-566; Package Size: 0603 (1608 Metric); Rated Voltage: 25V; Temperature Coefficient: X7R; Tolerance: 10%
DT9 = DIODE_TVS_DUAL: TVS DIODE 12V 25V SOT23-3; CLASS: DISCRETE; Company Part Status: New; Manufacturer: Comchip Technology; PART_NUMBER: TMP-1729; Package Size: TO-236-3, SC-59, SOT-23-3; Rated Power: 25W; Rated Voltage: 25 V
JT3 = CONN_DSUB_DE9: CONN D-SUB PLUG 9POS VERT SOLDER; CLASS: IO; Company Part Status: New; Contact Voltage: 600V; Manufacturer: Amphenol ICC (Commercial Products); Manufacturer PN: L777TSEG09POL2RM8; PART_NUMBER: TMP-1673
LT26 LT27 = IND_FB: Ferrite Bead, 1000 Ohm, 25 %, 0.05 A, 0603; CLASS: DISCRETE; Manufacturer: Murata; Manufacturer PN: BLM18HD102SN1B; PART_NUMBER: EMA-00005165V22; Package Size: 0603; Tolerance: 25 %
RT224 = R: RES SMD 120 OHM 5% 1/10W 0603; CLASS: DISCRETE; Company Part Status: New; Manufacturer: Yageo; Manufacturer PN: RC0603JR-07120RL; PART_NUMBER: TMP-619; Package Size: 0603 (1608 Metric); Rated Power: 0.1W, 1/10W; Temperature Coefficient: 100ppm/C; Tolerance: 5%
RT225-RT228 = R: RES 0.0 OHM 1/10W JUMP 0603 SMD; CLASS: DISCRETE; Company Part Status: New; Manufacturer: Yageo; Manufacturer PN: RC0603JR-070RL; PART_NUMBER: TMP-242; Package Size: 0603 (1608 Metric); Rated Power: 0.1W, 1/10W; Tolerance: Jumper
UT38 = ADM3057EBRWZ: CAN Interface IC 3.0kV isoPower CAN-FD Transceiver; CLASS: IC; Company Part Status: New; Manufacturer: Analog Devices; PART_NUMBER: TMP-1749; Package Size: SOIC-20; Rated Power: 2.35 W; Supply Voltage: 1.7 V to 5.5 V
DT4 = LED_0: LED RED DIFFUSED 0805 SMD; CLASS: DISCRETE; Company Part Status: New; Manufacturer: OSRAM Opto Semiconductors Inc.; PART_NUMBER: TMP-917; Package Size: 0805 (2012 Metric); Rated Voltage: 1.8V @ 20mA
DT5 = LED_0: LED YELLOW CLEAR 0805 SMD; CLASS: DISCRETE; Company Part Status: New; Manufacturer: Lite-On Inc.; PART_NUMBER: TMP-656; Package Size: 0805 (2012 Metric)
DT6 = LED_0: LED GREEN DIFFUSED 0805 SMD; CLASS: DISCRETE; Company Part Status: New; Manufacturer: OSRAM Opto Semiconductors Inc.; PART_NUMBER: TMP-915; Package Size: 0805 (2012 Metric); Rated Voltage: 2.2V
JT2 = CON20A: CONN HEADER 2.54MM 20POS GOLD; CLASS: IO; Company Part Status: Released; Manufacturer: Sullins Connector Solutions; PART_NUMBER: TMP-966
JT15 = CON2_v2: CONN HEADER VERT 2POS 2.54MM; CLASS: IO; Company Part Status: New; Contact Voltage: 675VAC, 954VDC; Manufacturer: Samtec Inc.; PART_NUMBER: TMP-1743
JT17 = CON14A: CONN HEADER VERT 14POS 2.54MM; CLASS: IO; Company Part Status: New; Manufacturer: Samtec Inc.; Manufacturer PN: TSW-107-07-T-D-006; PART_NUMBER: TMP-1753
JT26 = F28379D-ControlCard_1
RT53 RT54 RT78 RT229 RT236 RT238 RT243 = R: RES SMD 15K OHM 5% 1/10W 0603; CLASS: DISCRETE; Company Part Status: New; Manufacturer: Yageo; Manufacturer PN: RC0603JR-0715KL; PART_NUMBER: TMP-618; Package Size: 0603 (1608 Metric); Rated Power: 0.1W, 1/10W; Temperature Coefficient: 100ppm/C; Tolerance: 5%
RT152-RT154 = RES: RES SMD 680 OHM 1% 1/10W 0603; CLASS: DISCRETE; Company Part Status: New; Manufacturer: Yageo; Manufacturer PN: RC0603FR-07680RL; PART_NUMBER: TMP-1267; Package Size: 0603 (1608 Metric); Rated Power: 0.1W, 1/10W; Temperature Coefficient: 100ppm/C; Tolerance: 1%
UB15 UB17 UB20 = AND3_1X_6PIN: IC GATE AND 1CH 3-INP SOT23-6; CLASS: IC; Company Part Status: New; Manufacturer: Texas Instruments; PART_NUMBER: TMP-1521; Package Size: SOT-23-6; Supply Voltage: 1.65 V - 5.5 V
CB1-CB3 CT8-CT13 = CAP: CAP CER 100PF 50V 5% NP0 0603; CLASS: DISCRETE; Company Part Status: New; Dielectric Type: Capacitors; Manufacturer: Samsung Electro-Mechanics America, Inc; Manufacturer PN: CL10C101JB8NNNC; PART_NUMBER: TMP-455; Package Size: 0603 (1608 Metric); Rated Voltage: 50V; Temperature Coefficient: C0G, NP0; Tolerance: 5%
CB55-CB57 = CAP: CAP CER 4700PF 25V X7R 0603; CLASS: DISCRETE; Company Part Status: New; Dielectric Type: Capacitors; Manufacturer: Murata Electronics North America; Manufacturer PN: GCM188R71E472KA37D; PART_NUMBER: TMP-889; Package Size: 0603 (1608 Metric); Rated Voltage: 25V; Temperature Coefficient: X7R; Tolerance: 10%
CT28-CT30 CT44 CT53 CT61 CT71 = CAP: CAP CER 47PF 100V C0G/NP0 0603; CLASS: DISCRETE; Company Part Status: New; Manufacturer: KEMET; Manufacturer PN: C0603C470J1GACTU; PART_NUMBER: TMP-1716; Package Size: 0603 (1608 Metric); Rated Voltage: 100V; Temperature Coefficient: C0G, NP0; Tolerance: 5%
JB1 = ModularJack8P8C-shielded: CONN MOD JACK 8P8C VERT SHIELDED; CLASS: IO; Company Part Status: New; Contact Voltage: 150V; Manufacturer: Assmann WSW Components; PART_NUMBER: TMP-1660
RB7 RB9 RB11 RB15-RB17 = RES: RES SMD 20K OHM 1% 1/10W 0603; CLASS: DISCRETE; Company Part Status: Released; Manufacturer: Yageo; Manufacturer PN: RC0603FR-0720KL; PART_NUMBER: TMP-873; Package Size: 0603 (1608 Metric); Rated Power: 0.1W, 1/10W; Temperature Coefficient: 100ppm/C; Tolerance: 1%
RB8 RB10 RB12 RT33-RT35 = RES: Thick Film Resistors - SMD 0603 Anti-Surge Res. 0.1%, 27Kohm; CLASS: DISCRETE; Company Part Status: New; Manufacturer: Panasonic; Manufacturer PN: ERJ-PB3B2702V; PART_NUMBER: TMP-1751; Rated Power: 200 mW (1/5 W); Temperature Coefficient: 50 PPM / C; Tolerance: 0.1%
RT4-RT6 = RES_0: RES SMD 120 OHM 1% 1/10W 0603; CLASS: DISCRETE; Company Part Status: Released; Manufacturer: Yageo; Manufacturer PN: RC0603FR-07120RL; PART_NUMBER: TMP-957; Package Size: 0603 (1608 Metric); Rated Power: 0.1W, 1/10W; Temperature Coefficient: 100ppm/C; Tolerance: 1%
RT14-RT19 = RES: Thick Film Resistors - SMD 0603 Anti-Surge Res. 0.1%, 2.7Kohm; CLASS: DISCRETE; Company Part Status: New; Manufacturer: Panasonic; Manufacturer PN: ERJ-PB3B2701V; PART_NUMBER: TMP-1750; Rated Power: 200 mW (1/5 W); Temperature Coefficient: 50 PPM / C; Tolerance: 0.1%
RT21-RT26 = R: RES SMD 1K OHM 1% 1/10W 0603; CLASS: DISCRETE; Company Part Status: New; Manufacturer: Panasonic Electronic Components; Manufacturer PN: ERJ-3EKF1001V; PART_NUMBER: TMP-1344; Package Size: 0603 (1608 Metric); Rated Power: 0.1W, 1/10W; Temperature Coefficient: 100ppm/C; Tolerance: 1%
RB113-RB120 RT44-RT46 RT82 RT91 RT98 RT100 RT104 RT113 RT120 RT122 RT234 RT235 RT239 RT245 = RES: RES SMD 10K OHM 1% 1/10W 0603; CLASS: DISCRETE; Company Part Status: New; Manufacturer: Panasonic Electronic Components; Manufacturer PN: ERJ-3EKF1002V; PART_NUMBER: TMP-788; Package Size: 0603 (1608 Metric); Rated Power: 0.1W, 1/10W; Temperature Coefficient: 100ppm/C; Tolerance: 1%
RT50-RT52 = RES: RES SMD 49.9 OHM 1% 1/10W 0603; CLASS: DISCRETE; Company Part Status: New; Manufacturer: Panasonic Electronic Components; Manufacturer PN: ERJ-3EKF49R9V; PART_NUMBER: TMP-1252; Package Size: 0603 (1608 Metric); Rated Power: 0.1W, 1/10W; Temperature Coefficient: 100ppm/C; Tolerance: 1%
UB1 UB16 = REF2030: IC VREF SERIES 1.5V AND 3V 0.05% SOT23-5; CLASS: IC; Company Part Status: New; Manufacturer: Texas Instruments; Manufacturer PN: REF2030AIDDCT; PART_NUMBER: TMP-1708; Package Size: SOT-23-5 Thin, TSOT-23-5; Supply Voltage: 3 - 5.5 V
UT5 = OPAMP_4X_14P: IC OPAMP GP 24MHZ RRO 14TSSOP; CLASS: IC; Company Part Status: New; Manufacturer: Analog Devices Inc.; PART_NUMBER: TMP-1501; Package Size: 14-TSSOP (0.173", 4.40mm Width); PartGroup: CurrentU; Supply Voltage: 2.7 V - 5.5 V, 1.35 V - 2.75 V
UT6 = OPAMP_4X_14P: IC OPAMP GP 24MHZ RRO 14TSSOP; CLASS: IC; Company Part Status: New; Manufacturer: Analog Devices Inc.; PART_NUMBER: TMP-1501; Package Size: 14-TSSOP (0.173", 4.40mm Width); PartGroup: CurrentV; Supply Voltage: 2.7 V - 5.5 V, 1.35 V - 2.75 V
UT7 = OPAMP_4X_14P: IC OPAMP GP 24MHZ RRO 14TSSOP; CLASS: IC; Company Part Status: New; Manufacturer: Analog Devices Inc.; PART_NUMBER: TMP-1501; Package Size: 14-TSSOP (0.173", 4.40mm Width); PartGroup: CurrentW; Supply Voltage: 2.7 V - 5.5 V, 1.35 V - 2.75 V
CT37 CT40 CT45 CT54 CT63 CT72 CT103 CT159 CT164 CT165 = CAP: CAP CER 1000PF 50V C0G/NP0 0603; CLASS: DISCRETE; Company Part Status: New; Dielectric Type: Capacitors; Manufacturer: Murata Electronics North America; Manufacturer PN: GRM1885C1H102FA01J; PART_NUMBER: TMP-1524; Package Size: 0603 (1608 Metric); Rated Voltage: 50V; Temperature Coefficient: C0G, NP0; Tolerance: 1%
CT46 CT49 CT55 CT57 CT64 CT67 CT73 CT75 = CAP: CAP CER 330PF 250V C0G/NP0 0603; CLASS: DISCRETE; Company Part Status: New; Manufacturer: KEMET; Manufacturer PN: C0603C331JAGAC7867; PART_NUMBER: TMP-1715; Package Size: 0603 (1608 Metric); Rated Voltage: 250V; Temperature Coefficient: C0G, NP0; Tolerance: 5%
CT157 CT158 CT162 CT166 = CAP: CAP CER 18PF 50V NP0 0603; CLASS: DISCRETE; Company Part Status: New; Dielectric Type: Capacitors; Manufacturer: AVX Corporation; Manufacturer PN: 06035A180JAT2A; PART_NUMBER: TMP-718; Package Size: 0603 (1608 Metric); Rated Voltage: 50V; Temperature Coefficient: C0G, NP0; Tolerance: 5%
DT10-DT15 = DIODE_QUAD_A1_C2_C1A2: DIODE ARRAY SCHOTTKY 40V SOT23-3; CLASS: DISCRETE; Company Part Status: New; Manufacturer: Diodes Incorporated; Manufacturer PN: BAS40-04-7-F; PART_NUMBER: TMP-1744; Package Size: TO-236-3, SC-59, SOT-23-3; Rated Power: 350 mW; Rated Voltage: 1V @ 40mA
JT18 JT22 = HEADER_3X2: CONN HEADER VERT 6POS 2.54MM; CLASS: IO; Company Part Status: New; Contact Voltage: 250V; Manufacturer: Würth Elektronik; PART_NUMBER: TMP-1752
QT4 QT5 = BJT_NPN_BEC: TRANS NPN 45V 0.5A SOT-23; CLASS: DISCRETE; Company Part Status: Released; Manufacturer: ON Semiconductor; PART_NUMBER: TMP-1002; Package Size: TO-236-3, SC-59, SOT-23-3; Polarity: NPN; Rated Power: 300mW
RT79 RT81 RT93 RT96 RT101 RT103 RT115 RT119 = RES: RES SMD 12.1K OHM 0.1% 1/5W 0603; CLASS: DISCRETE; Company Part Status: New; Manufacturer: Panasonic Electronic Components; Manufacturer PN: ERJ-PB3B1212V; PART_NUMBER: TMP-1717; Package Size: 0603 (1608 Metric); Rated Power: 0.2W, 1/5W; Temperature Coefficient: 50ppm/C; Tolerance: 0.1%
RT80 RT95 RT102 RT117 = RES: RES SMD 47K OHM 1% 1/10W 0603; CLASS: DISCRETE; Company Part Status: New; Manufacturer: Yageo; Manufacturer PN: RC0603FR-0747KL; PART_NUMBER: TMP-1718; Package Size: 0603 (1608 Metric); Rated Power: 0.1W, 1/10W; Temperature Coefficient: 100ppm/C; Tolerance: 1%
RT66 RT75 RT83 RT99 RT105 RT121 = RES: RES SMD 2K OHM 1% 1/10W 0603; CLASS: DISCRETE; Company Part Status: New; Manufacturer: Yageo; Manufacturer PN: RC0603FR-072KL; PART_NUMBER: TMP-1519; Package Size: 0603 (1608 Metric); Rated Power: 0.1W, 1/10W; Temperature Coefficient: 100ppm/C; Tolerance: 1%
RT163 RT164 RT242 RT246 = RES: Thick Film Resistors - SMD 3.9K OHM 5%; CLASS: DISCRETE; Company Part Status: New; Manufacturer: Yageo; Manufacturer PN: RC0603JR-073K9L; PART_NUMBER: TMP-1748; Rated Power: 100 mW (1/10 W); Temperature Coefficient: 100 PPM / C; Tolerance: 5%
RT230 RT233 RT237 RT244 = RES: Thick Film Resistors - SMD 470K OHM 1%; CLASS: DISCRETE; Company Part Status: New; Manufacturer: Yageo; Manufacturer PN: RC0603FR-07470KL; PART_NUMBER: TMP-1746; Rated Power: 100 mW (1/10 W); Temperature Coefficient: 100 PPM / C; Tolerance: 1%
RT247 RT249 RT250 RT252 = R: RES SMD 120K OHM 1% 1/10W 0603; CLASS: DISCRETE; Company Part Status: New; Manufacturer: Yageo; Manufacturer PN: RC0603FR-07120KL; PART_NUMBER: TMP-1410; Package Size: 0603 (1608 Metric); Rated Power: 0.1W, 1/10W; Temperature Coefficient: 100ppm/C; Tolerance: 1%
RT248 RT251 = RES: Thick Film Resistors - SMD 20 OHM 5%; CLASS: DISCRETE; Company Part Status: New; Manufacturer: Yageo; Manufacturer PN: RC0603JR-0720RL; PART_NUMBER: TMP-1747; Rated Power: 100 mW (1/10 W); Temperature Coefficient: 100 PPM / C; Tolerance: 5%
UT13 UT15 UT17 UT19 UT39 UT40 = AD8615: IC OPAMP GP 24MHZ RRO TSOT23-5; CLASS: IC; Company Part Status: New; Manufacturer: Analog Devices Inc.; PART_NUMBER: TMP-1499; Package Size: SOT-23-5 Thin, TSOT-23-5; Supply Voltage: 2.7 V - 5.5 V, 1.35 V - 2.75 V
UT41 UT43 = ALM2402FQPWPRQ1: IC OPAMP GP 2 CIRCUIT 14HTSSOP; CLASS: IC; Company Part Status: New; Manufacturer: Texas Instruments; PART_NUMBER: TMP-1745; Package Size: 14-TSSOP (0.173", 4.40mm Width) Exposed Pad; Supply Voltage: 4.5V ~ 16V, 2.25V ~ 8V
JT4-JT14 JT16 JT19-JT21 JT23-JT25 JT27-JT40 = BNC_5P: CONN MMCX JACK STR 50 OHM PCB; CLASS: IO; Company Part Status: Released; Contact Voltage: 500V; Manufacturer: Samtec Inc.; PART_NUMBER: TMP-1696

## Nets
+1V5REF_RSLV: CB46.1 CT48.1 CT49.1 CT56.1 CT57.1 CT66.1 CT67.1 CT74.1 CT75.1 RT91.2 RT100.2 RT113.2 RT122.2 UB16.1(VREF/2)
+3V3: CB5.1 CB36.1 CB43.1 CB54.1 CB68.1 CT33.1 CT43.1 CT51.1 CT60.1 CT69.1 CT156.1 CT160.1 CT163.1 JT2.7 JT17.5 RB113.1 RB118.1 RT53.2 RT54.2 RT78.1 RT229.2 RT238.2 UB1.3(EN) UB1.4(VIN) UB15.5(VCC) UB16.3(EN) UB16.4(VIN) UB17.5(VCC) UB20.5(VCC) UT13.5(V+) UT15.5(V+) UT17.5(V+) UT19.5(V+) UT38.4(VIO) UT39.5(V+) UT40.5(V+) ; also on sheet 7 8 9 10 11 13 14 15 16
+3VREF_A: CB4.1 RB15.1 RB16.1 RB17.1 UB1.5(VREF)
+5V: CT22.1 CT23.1 CT24.1 CT150.1 CT153.1 JB1.2 JT26.48(5V0#48) JT26.84(5V0#84) JT26.98(5V0#98) JT26.112(5V0#112) JT26.158(5V0#158) JT26.180(5V0#180) UT5.4(VCC) UT6.4(VCC) UT7.4(VCC) UT38.3(VCC) ; also on sheet 7 8 9 10 11
+5V-ISO: CT151.1 CT154.1 CT155.1 JT3.9 LT26.2 UT38.16(VISOIN)
+12V: JT2.1 ; also on sheet 8 9 10
+15V: CT95.1 CT161.1 DT10.2(A1) DT10.5(A1) DT11.2(A1) DT11.5(A1) DT12.2(A1) DT12.5(A1) DT13.2(A1) DT13.5(A1) DT14.2(A1) DT14.5(A1) DT15.2(A1) DT15.5(A1) RB114.1 RB117.1 RT235.1 RT239.1 UT41.10(VS_O(2)) UT41.11(VS) UT41.12(VS_O(1)) UT43.10(VS_O(2)) UT43.11(VS) UT43.12(VS_O(1)) ; also on sheet 10
0: CB1.1 CB2.1 CB3.1 CB4.2 CB5.2 CB6.2 CB36.2 CB43.2 CB46.2 CB47.2 CB54.2 CB55.2 CB56.2 CB57.2 CB68.2 CB79.2 CB81.2 CB83.2 CB84.2 CT8.2 CT9.1 CT10.2 CT11.1 CT12.2 CT13.1 CT22.2 CT23.2 CT24.2 CT33.2 CT37.2 CT40.2 CT43.2 CT45.2 CT48.2 CT51.2 CT54.2 CT56.2 CT60.2 CT63.2 CT66.2 CT69.2 CT72.2 CT74.2 CT95.2 CT103.1 CT150.2 CT153.2 CT156.2 CT160.2 CT161.2 CT163.2 CT164.1 DT4.2(C) DT5.2(C) DT6.2(C) DT10.1(C2) DT10.4(C2) DT11.1(C2) DT11.4(C2) DT12.1(C2) DT12.4(C2) DT13.1(C2) DT13.4(C2) DT14.1(C2) DT14.4(C2) DT15.1(C2) DT15.4(C2) JB1.1 JB1.S1(SHIELD) JT2.2 JT2.8 JT4.2(GND1) JT4.3(GND2) JT4.4(GND3) JT4.5(GND4) JT5.2(GND1) JT5.3(GND2) JT5.4(GND3) JT5.5(GND4) JT6.2(GND1) JT6.3(GND2) JT6.4(GND3) JT6.5(GND4) JT7.2(GND1) JT7.3(GND2) JT7.4(GND3) JT7.5(GND4) JT8.2(GND1) JT8.3(GND2) JT8.4(GND3) JT8.5(GND4) JT9.2(GND1) JT9.3(GND2) JT9.4(GND3) JT9.5(GND4) JT10.2(GND1) JT10.3(GND2) JT10.4(GND3) JT10.5(GND4) JT11.2(GND1) JT11.3(GND2) JT11.4(GND3) JT11.5(GND4) JT12.2(GND1) JT12.3(GND2) JT12.4(GND3) JT12.5(GND4) JT13.2(GND1) JT13.3(GND2) JT13.4(GND3) JT13.5(GND4) JT14.2(GND1) JT14.3(GND2) JT14.4(GND3) JT14.5(GND4) JT15.2 JT16.2(GND1) JT16.3(GND2) JT16.4(GND3) JT16.5(GND4) JT17.4 JT17.8 JT17.10 JT17.12 JT19.2(GND1) JT19.3(GND2) JT19.4(GND3) JT19.5(GND4) JT20.2(GND1) JT20.3(GND2) JT20.4(GND3) JT20.5(GND4) JT21.2(GND1) JT21.3(GND2) JT21.4(GND3) JT21.5(GND4) JT23.2(GND1) JT23.3(GND2) JT23.4(GND3) JT23.5(GND4) JT24.2(GND1) JT24.3(GND2) JT24.4(GND3) JT24.5(GND4) JT25.2(GND1) JT25.3(GND2) JT25.4(GND3) JT25.5(GND4) JT26.7(GND#7) JT26.10(GND#10) JT26.13(GND#13) JT26.16(GND#16) JT26.19(GND#19) JT26.22(GND#22) JT26.29(GND#29) JT26.35(GND#35) JT26.38(GND#38) JT26.46(GND#46) JT26.47(GND#47) JT26.65(GND#65) JT26.83(GND#83) JT26.97(GND#97) JT26.111(GND#111) JT26.135(GND#135) JT26.157(GND#157) JT26.179(GND#179) JT26.G1 JT26.G2 JT26.G3 JT26.G4 JT27.2(GND1) JT27.3(GND2) JT27.4(GND3) JT27.5(GND4) JT28.2(GND1) JT28.3(GND2) JT28.4(GND3) JT28.5(GND4) JT29.2(GND1) JT29.3(GND2) JT29.4(GND3) JT29.5(GND4) JT30.2(GND1) JT30.3(GND2) JT30.4(GND3) JT30.5(GND4) JT31.2(GND1) JT31.3(GND2) JT31.4(GND3) JT31.5(GND4) JT32.2(GND1) JT32.3(GND2) JT32.4(GND3) JT32.5(GND4) JT33.2(GND1) JT33.3(GND2) JT33.4(GND3) JT33.5(GND4) JT34.2(GND1) JT34.3(GND2) JT34.4(GND3) JT34.5(GND4) JT35.2(GND1) JT35.3(GND2) JT35.4(GND3) JT35.5(GND4) JT36.2(GND1) JT36.3(GND2) JT36.4(GND3) JT36.5(GND4) JT37.2(GND1) JT37.3(GND2) JT37.4(GND3) JT37.5(GND4) JT38.2(GND1) JT38.3(GND2) JT38.4(GND3) JT38.5(GND4) JT39.2(GND1) JT39.3(GND2) JT39.4(GND3) JT39.5(GND4) JT40.2(GND1) JT40.3(GND2) JT40.4(GND3) JT40.5(GND4) RB7.2 RB9.2 RB11.2 RB115.2 RB116.2 RB119.2 RB120.2 RT225.2 RT226.2 RT227.2 RT234.2 RT245.2 UB1.2(GND) UB15.2(GND) UB16.2(GND) UB17.2(GND) UB20.2(GND) UT5.2(IN1-) UT5.3(IN1+) UT5.11(GND) UT6.2(IN1-) UT6.3(IN1+) UT6.11(GND) UT7.2(IN1-) UT7.3(IN1+) UT7.11(GND) UT13.2(V-) UT15.2(V-) UT17.2(V-) UT19.2(V-) UT38.1(GND1) UT38.2(GND1_1) UT38.10(GND1_2) UT39.2(V-) UT40.2(V-) UT41.6(GND) UT41.14(GND_1) UT41.EPAD UT43.6(GND) UT43.14(GND_1) UT43.EPAD ; also on sheet 7 8 9 10 11 13 14 15 16
1: CT151.2 CT154.2 CT155.2 DT9.3(A3) JT3.3 JT3.5 JT3.10(Shield) LT27.2 RT228.2 UT38.11(GND2) UT38.15(GND2_1)
CANA-H: DT9.1(A1) JT3.7 RT224.1 UT38.14(CANH)
CANA-L: DT9.2(A2) JT3.2 RT224.2 UT38.13(CANL)
CANA-RX: JT26.80(CANRXA) UT38.5(RXD)
CANA-TX: JT26.82(CANTXA) UT38.7(TXD)
CASE-TEMP: JT26.30(ADC-D1) ; also on sheet 13
COS-A: CT54.1 JT20.1(SIGNAL) JT26.36(ADC-D3) RT99.2
COS-A-N: CT53.1 CT57.2 DT13.3(C1A2) JT18.6 RT95.1 RT96.1 RT100.1
COS-A-P: CT53.2 DT13.6(C1A2) JT18.5 RT93.1 RT95.2
COS-B: CT72.1 JT26.42(ADC-D5) JT27.1(SIGNAL) RT121.2
COS-B-N: CT71.1 CT75.2 DT10.3(C1A2) JT22.6 RT117.1 RT119.1 RT122.1
COS-B-P: CT71.2 DT10.6(C1A2) JT22.5 RT115.1 RT117.2
Current-U: CB55.1 JT11.1(SIGNAL) JT26.12(ADC-B0) RT50.2
Current-U_N: JB1.3 RT4.2 RT14.1
Current-U_P: JB1.6 RT4.1 RT15.1
Current-V: CB56.1 JT4.1(SIGNAL) JT26.14(ADC-B1) RT51.2
Current-V_N: JB1.5 RT5.2 RT16.1
Current-V_P: JB1.4 RT5.1 RT17.1
Current-W: CB57.1 JT12.1(SIGNAL) JT26.18(ADC-B2) RT52.2
Current-W_N: JB1.7 RT6.2 RT18.1
Current-W_P: JB1.8 RT6.1 RT19.1
Current-X: JT26.26(ADC-B5) JT40.1(SIGNAL) ; also on sheet 7
Current-Y: JT26.24(ADC-B4) JT39.1(SIGNAL) ; also on sheet 7
Current-Z: JT26.20(ADC-B3) JT38.1(SIGNAL) ; also on sheet 7
EMUI: JT17.14 JT26.1(JTAG-EMU1)
EMUO: JT17.13 JT26.2(JTAG-EMU0)
EXC-A-N: CT158.2 DT15.3(C1A2) JT18.2 RT233.2 UT41.9(OUT(2))
EXC-A-P: CT157.2 DT15.6(C1A2) JT18.1 RT230.2 UT41.13(OUT(1))
EXC-B-N: CT166.2 DT12.3(C1A2) JT22.2 RT244.2 UT43.9(OUT(2))
EXC-B-P: CT162.2 DT12.6(C1A2) JT22.1 RT237.2 UT43.13(OUT(1))
Global-FAULT-ALL: JT16.1(SIGNAL) JT26.134(GPIO-69) UB17.4(Y)
Global-FAULT-UVW: JT26.130(GPIO-65) UB15.4(Y) UB17.3(B)
Global-FAULT-XYZ: JT26.132(GPIO-67) UB17.6(C) UB20.4(Y)
I2CA-SCL: JT2.9 JT26.87(I2C-SCLA) RT54.1
I2CA-SDA: JT2.10 JT26.85(I2C-SDAA) RT53.1
LED-G: JT26.133(GPIO-68) RT154.1
LED-R: JT26.129(GPIO-64) RT152.1
LED-Y: JT26.131(GPIO-66) RT153.1
PWM7A: JT2.12 JT26.58(PWM7A)
PWM7B: JT2.11 JT26.60(PWM7B)
PWM8A: JT2.14 JT26.62(PWM8A)
PWM8B: JT2.13 JT26.64(PWM8B)
PWM9A: JT26.167(GPIO-161) RT66.1
PWM9B: JT26.168(GPIO-162) RT75.1
QEA_A: JT26.68(QEP1A) ; also on sheet 11
QEA_B: JT26.70(QEP1B) ; also on sheet 11
QEA_I: JT26.74(QEP1I) ; also on sheet 11
QEB_A: JT26.100(QEP2A) ; also on sheet 11
QEB_B: JT26.102(QEP2B) ; also on sheet 11
QEB_I: JT26.106(QEP2I) ; also on sheet 11
RSLV-A-PWM: JT26.169(GPIO-163) RT163.1
RSLV-B-PWM: JT26.170(GPIO-164) RT242.1
SD-C1: JT2.15 JT26.101(SD-C1)
SD-C2: JT2.17 JT26.105(SD-C2)
SD-C3: JT2.19 JT26.109(SD-C3)
SD-D1: JT2.16 JT26.99(SD-D1)
SD-D2: JT2.18 JT26.103(SD-D2)
SD-D3: JT2.20 JT26.107(SD-D3)
Shutdown+15V: JT26.155(GPIO-88) ; also on sheet 10
SIN-A: CT45.1 JT19.1(SIGNAL) JT26.34(ADC-D2) RT83.2
SIN-A-N: CT44.1 CT49.2 DT14.3(C1A2) JT18.4 RT80.1 RT81.1 RT91.1
SIN-A-P: CT44.2 DT14.6(C1A2) JT18.3 RT79.1 RT80.2
SIN-B: CT63.1 JT23.1(SIGNAL) JT26.40(ADC-D4) RT105.2
SIN-B-N: CT61.1 CT67.2 DT11.3(C1A2) JT22.4 RT102.1 RT103.1 RT113.1
SIN-B-P: CT61.2 DT11.6(C1A2) JT22.3 RT101.1 RT102.2
SPIA-CLK: JT2.6 JT26.71(SPI-CLKA)
SPIA-MISO: JT2.5 JT26.69(SPI-MISOA)
SPIA-MOSI: JT2.3 JT26.67(SPI-MOSIA)
SPIA-STE: JT2.4 JT26.73(SPI-STEA)
TCK: JT17.9 JT17.11 JT26.5(JTAG-TCK)
TDI: JT17.3 JT26.8(JTAG-TDI)
TDO: JT17.7 JT26.6(JTAG-TDO)
TMS: JT17.1 JT26.3(JTAG-TMS)
TRST: JT17.2 JT26.4(JTAG-TRSTN)
U-FAULT: JT26.122(GPIO-36) UB15.1(A) ; also on sheet 8
U-LEN-OUT: JT26.144(GPIO-77) ; also on sheet 8
U-OCEN-OUT: JT26.142(GPIO-75) ; also on sheet 8
U-PSDIS-OUT: JT26.146(GPIO-79) ; also on sheet 8
U-RTD: JT26.92(GPIO-45) ; also on sheet 8 13
U-TEMP: JT26.25(ADCIN14) ; also on sheet 13
UHS-PWM: JT9.1(SIGNAL) JT26.49(PWM1A) ; also on sheet 8
ULS-PWM: JT10.1(SIGNAL) JT26.51(PWM1B) ; also on sheet 8
V-FAULT: JT26.124(GPIO-38) UB15.3(B) ; also on sheet 8
V-LEN-OUT: JT26.152(GPIO-85) ; also on sheet 8
V-OCEN-OUT: JT26.150(GPIO-83) ; also on sheet 8
V-PSDIS-OUT: JT26.154(GPIO-87) ; also on sheet 8
V-RTD: JT26.94(GPIO-46) ; also on sheet 8 13
V-TEMP: JT26.27(ADCIN15) ; also on sheet 13
VHS-PWM: JT7.1(SIGNAL) JT26.53(PWM2A) ; also on sheet 8
VLS-PWM: JT8.1(SIGNAL) JT26.55(PWM2B) ; also on sheet 8
Vsense-DC: JT21.1(SIGNAL) JT26.28(ADC-D0) ; also on sheet 15
Vsense-U: JT24.1(SIGNAL) JT26.9(ADC-A0) ; also on sheet 14
Vsense-V: JT25.1(SIGNAL) JT26.11(ADC-A1) ; also on sheet 14
Vsense-W: JT26.15(ADC-A2) JT28.1(SIGNAL) ; also on sheet 14
Vsense-X: JT26.17(ADC-A3) JT29.1(SIGNAL) ; also on sheet 16
Vsense-Y: JT26.21(ADC-A4) JT30.1(SIGNAL) ; also on sheet 16
Vsense-Z: JT26.23(ADC-A5) JT31.1(SIGNAL) ; also on sheet 16
W-FAULT: JT26.126(GPIO-61) UB15.6(C) ; also on sheet 8
W-LEN-OUT: JT26.162(GPIO-93) ; also on sheet 8
W-OCEN-OUT: JT26.160(GPIO-91) ; also on sheet 8
W-PSDIS-OUT: JT26.164(GPIO-133) ; also on sheet 8
W-RTD: JT26.96(GPIO-47) ; also on sheet 8 13
W-TEMP: JT26.31(ADC-C2) ; also on sheet 13
WHS-PWM: JT5.1(SIGNAL) JT26.50(PWM3A) ; also on sheet 8
WLS-PWM: JT6.1(SIGNAL) JT26.52(PWM3B) ; also on sheet 8
X-FAULT: JT26.121(GPIO-35) UB20.1(A) ; also on sheet 9
X-LEN-OUT: JT26.143(GPIO-76) ; also on sheet 9
X-OCEN-OUT: JT26.141(GPIO-74) ; also on sheet 9
X-PSDIS-OUT: JT26.145(GPIO-78) ; also on sheet 9
X-RTD: JT26.89(GPIO-40) ; also on sheet 9 13
X-TEMP: JT26.33(ADC-C3) ; also on sheet 13
XHS-PWM: JT26.54(PWM4A) JT36.1(SIGNAL) ; also on sheet 9
XLS-PWM: JT26.56(PWM4B) JT37.1(SIGNAL) ; also on sheet 9
Y-FAULT: JT26.123(GPIO-37) UB20.3(B) ; also on sheet 9
Y-LEN-OUT: JT26.151(GPIO-84) ; also on sheet 9
Y-OCEN-OUT: JT26.149(GPIO-82) ; also on sheet 9
Y-PSDIS-OUT: JT26.153(GPIO-86) ; also on sheet 9
Y-RTD: JT26.91(GPIO-41) ; also on sheet 9 13
Y-TEMP: JT26.37(ADC-C4) ; also on sheet 13
YHS-PWM: JT26.57(PWM5A) JT34.1(SIGNAL) ; also on sheet 9
YLS-PWM: JT26.59(PWM5B) JT35.1(SIGNAL) ; also on sheet 9
Z-FAULT: JT26.125(GPIO-60) UB20.6(C) ; also on sheet 9
Z-LEN-OUT: JT26.161(GPIO-92) ; also on sheet 9
Z-OCEN-OUT: JT26.159(GPIO-90) ; also on sheet 9
Z-PSDIS-OUT: JT26.163(GPIO-94) ; also on sheet 9
Z-RTD: JT26.93(GPIO-42) ; also on sheet 9 13
Z-TEMP: JT26.39(ADC-C5) ; also on sheet 13
ZHS-PWM: JT26.61(PWM6A) JT32.1(SIGNAL) ; also on sheet 9
ZLS-PWM: JT26.63(PWM6B) JT33.1(SIGNAL) ; also on sheet 9
N93191: DT4.1(A) RT152.2
N93195: DT6.1(A) RT154.2
N93199: DT5.1(A) RT153.2
N4877770: CT8.1 RT14.2 RT21.1
N4877774: CT9.2 RT15.2 RT22.1
N4883221: RT22.2 UT5.5(IN2+)
N4883225: RB8.1 UT5.6(IN2-) UT5.7(OUT2)
N4883237: RT21.2 UT5.10(IN3+)
N4883249: RT33.1 UT5.8(OUT3) UT5.9(IN3-)
N4883601: CT28.1 RT33.2 RT44.1 UT5.13(IN4-)
N4883608: CT28.2 RT44.2 RT50.1 UT5.14(OUT4)
N4883677: CB1.2 RB7.1 RB8.2 RB15.2 UT5.12(IN4+)
N4893553: CB2.2 RB9.1 RB10.2 RB16.2 UT6.12(IN4+)
N4893669: CT11.2 RT17.2 RT24.1
N4893747: RT24.2 UT6.5(IN2+)
N4893767: RB10.1 UT6.6(IN2-) UT6.7(OUT2)
N4893837: CT29.2 RT45.2 RT51.1 UT6.14(OUT4)
N4893845: CT29.1 RT34.2 RT45.1 UT6.13(IN4-)
N4893923: CT10.1 RT16.2 RT23.1
N4893935: RT23.2 UT6.10(IN3+)
N4893955: RT34.1 UT6.8(OUT3) UT6.9(IN3-)
N4894909: CB3.2 RB11.1 RB12.2 RB17.2 UT7.12(IN4+)
N4895025: CT13.2 RT19.2 RT26.1
N4895103: RT26.2 UT7.5(IN2+)
N4895123: RB12.1 UT7.6(IN2-) UT7.7(OUT2)
N4895193: CT30.2 RT46.2 RT52.1 UT7.14(OUT4)
N4895201: CT30.1 RT35.2 RT46.1 UT7.13(IN4-)
N4895279: CT12.1 RT18.2 RT25.1
N4895291: RT25.2 UT7.10(IN3+)
N4895311: RT35.1 UT7.8(OUT3) UT7.9(IN3-)
N4909322: JT15.1 RT78.2 UB17.1(A)
N5215633: RT81.2 UT13.3(IN+)
N5215739: CT46.2 RT82.2 RT83.1 UT13.1(OUT)
N5215763: CT46.1 RT79.2 RT82.1 UT13.4(IN-)
N5219233: CB47.1 UB16.5(VREF)
N5220223: RT96.2 UT15.3(IN+)
N5220393: CT55.2 RT98.2 RT99.1 UT15.1(OUT)
N5220405: CT55.1 RT93.2 RT98.1 UT15.4(IN-)
N5225791: CB6.1 UB1.1(VREF/2)
N5227646: RT103.2 UT17.3(IN+)
N5227670: CT64.2 RT104.2 RT105.1 UT17.1(OUT)
N5227676: CT64.1 RT101.2 RT104.1 UT17.4(IN-)
N5227730: RT119.2 UT19.3(IN+)
N5227754: CT73.2 RT120.2 RT121.1 UT19.1(OUT)
N5227760: CT73.1 RT115.2 RT120.1 UT19.4(IN-)
N5284170: CT37.1 JT13.1(SIGNAL) RT66.2
N5287176: CT40.1 JT14.1(SIGNAL) RT75.2
N5377291: RT228.1 UT38.12(RS)
N5387179: CT152.2 LT27.1 UT38.18(GNDISO) UT38.20(GNDISO_1)
N5387193: CT152.1 LT26.1 UT38.19(VISOOUT)
N5390614: RT227.1 UT38.9(AUXIN)
N5390858: RT226.1 UT38.8(STBY)
N5390867: RT225.1 UT38.6(SILENT)
N5429427: RT229.1 UT41.3(OTF/SH_DN)
N5429751: CT157.1 RT230.1 RT247.2 UT41.1(IN(1)-)
N5430286: CB79.1 RB114.2 RB116.1 UT41.2(IN(1)+) UT41.4(IN(2)+)
N5430623: CT158.1 RT233.1 RT249.2 UT41.5(IN(2)-)
N5431331: CT169.1 RT247.1
N5431438: CT170.1 RT249.1
N5432011: CT103.2 RT163.2 RT164.1 RT236.1
N5433071: QT5.3(C) RT248.2
N5433075: CT169.2 RT235.2 RT248.1
N5433096: CT170.2 QT5.2(E) RT234.1
N5433357: CT159.2 QT5.1(B) RT164.2 UT39.1(OUT)
N5434399: CT159.1 RT236.2 UT39.4(IN-)
N5434918: CB83.1 RB113.2 RB115.1 UT39.3(IN+)
N5437148: CT162.1 RT237.1 RT250.2 UT43.1(IN(1)-)
N5437220: CT167.2 RT239.2 RT251.1
N5437228: CT167.1 RT250.1
N5437378: RT238.1 UT43.3(OTF/SH_DN)
N5437474: CB81.1 RB117.2 RB120.1 UT43.2(IN(1)+) UT43.4(IN(2)+)
N5437598: CT166.1 RT244.1 RT252.2 UT43.5(IN(2)-)
N5437614: QT4.3(C) RT251.2
N5437712: CB84.1 RB118.2 RB119.1 UT40.3(IN+)
N5437790: CT165.2 QT4.1(B) RT246.2 UT40.1(OUT)
N5437806: CT164.2 RT242.2 RT243.1 RT246.1
N5437826: CT165.1 RT243.2 UT40.4(IN-)
N5437838: CT168.2 QT4.2(E) RT245.1
N5437898: CT168.1 RT252.1

Not connected (* = marked no-connect by the designer): JB1 S2(SHIELD2); JT3 1* 4* 6* 8* 11(Shield1); JT17 6*; JT26 32(RSV#32) 41(RSV#41) 43(VREFLO) 44(RSV#44) 45(VREFHI) 66(RSV#66) 72(QEP1S) 75(SPI-MOSIB) 76(UART-RXA) 77(SPI-MISOB) 78(UART-TXA) 79(SPI-CLKB) 81(SPI-STEB) 86(GPIO-34) 88(GPIO-39) 90(GPIO-44) 95(GPIO-43) 104(QEP2S) 108(GPIO-58) 110(GPIO-59) 113(RSV#113) 114(RSV#114) 115(RSV#115) 116(RSV#116) 117(RSV#117) 118(RSV#118) 119(RSV#119) 120(nRESET) 127(GPIO-62) 128(GPIO-63) 136(RSV#136) 137(GPIO-70) 138(GPIO-71) 139(GPIO-72) 140(GPIO-73) 147(GPIO-80) 148(GPIO-81) 156(GPIO-89) 165(GPIO-120)* 166(GPIO-121)* 171(RSV#171) 172(RSV#172) 173(RSV#173) 174(RSV#174) 175(RSV#175) 176(RSV#176) 177(RSV#177) 178(RSV#178); UT5 1(OUT1); UT6 1(OUT1); UT7 1(OUT1); UT38 17(AUXOUT); UT41 7(NC)* 8(NC_1)*; UT43 7(NC)* 8(NC_1)*

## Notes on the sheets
sheet 1
- RESOLVER B
sheet 2
- 1.5V Bias for Resolvers A and B
- RESOLVER A
sheet 3
- TEST POINTS:
  12 PWM
  6 Current
  7 Voltage
  1 Fault
  2 PWM DAC
  4 Resolver
sheet 4
- CiA DS102
- BK1608LM182-T
- Mating Connector:
  909GME-ND
  209FER-ND
sheet 5
- Amphenol, 609-5622-ND
- 0805 Red Diff
- 0805 Yellow Clear
  1.8V @ 5mA
- 0805 Green Diff
- Ext Estop
- Expansion Header
sheet 6
- 3V Bias for Current Sensors UVW
